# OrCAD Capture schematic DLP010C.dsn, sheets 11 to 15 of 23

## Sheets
11 PAGE 10 - DLPC410 - 2: size Custom
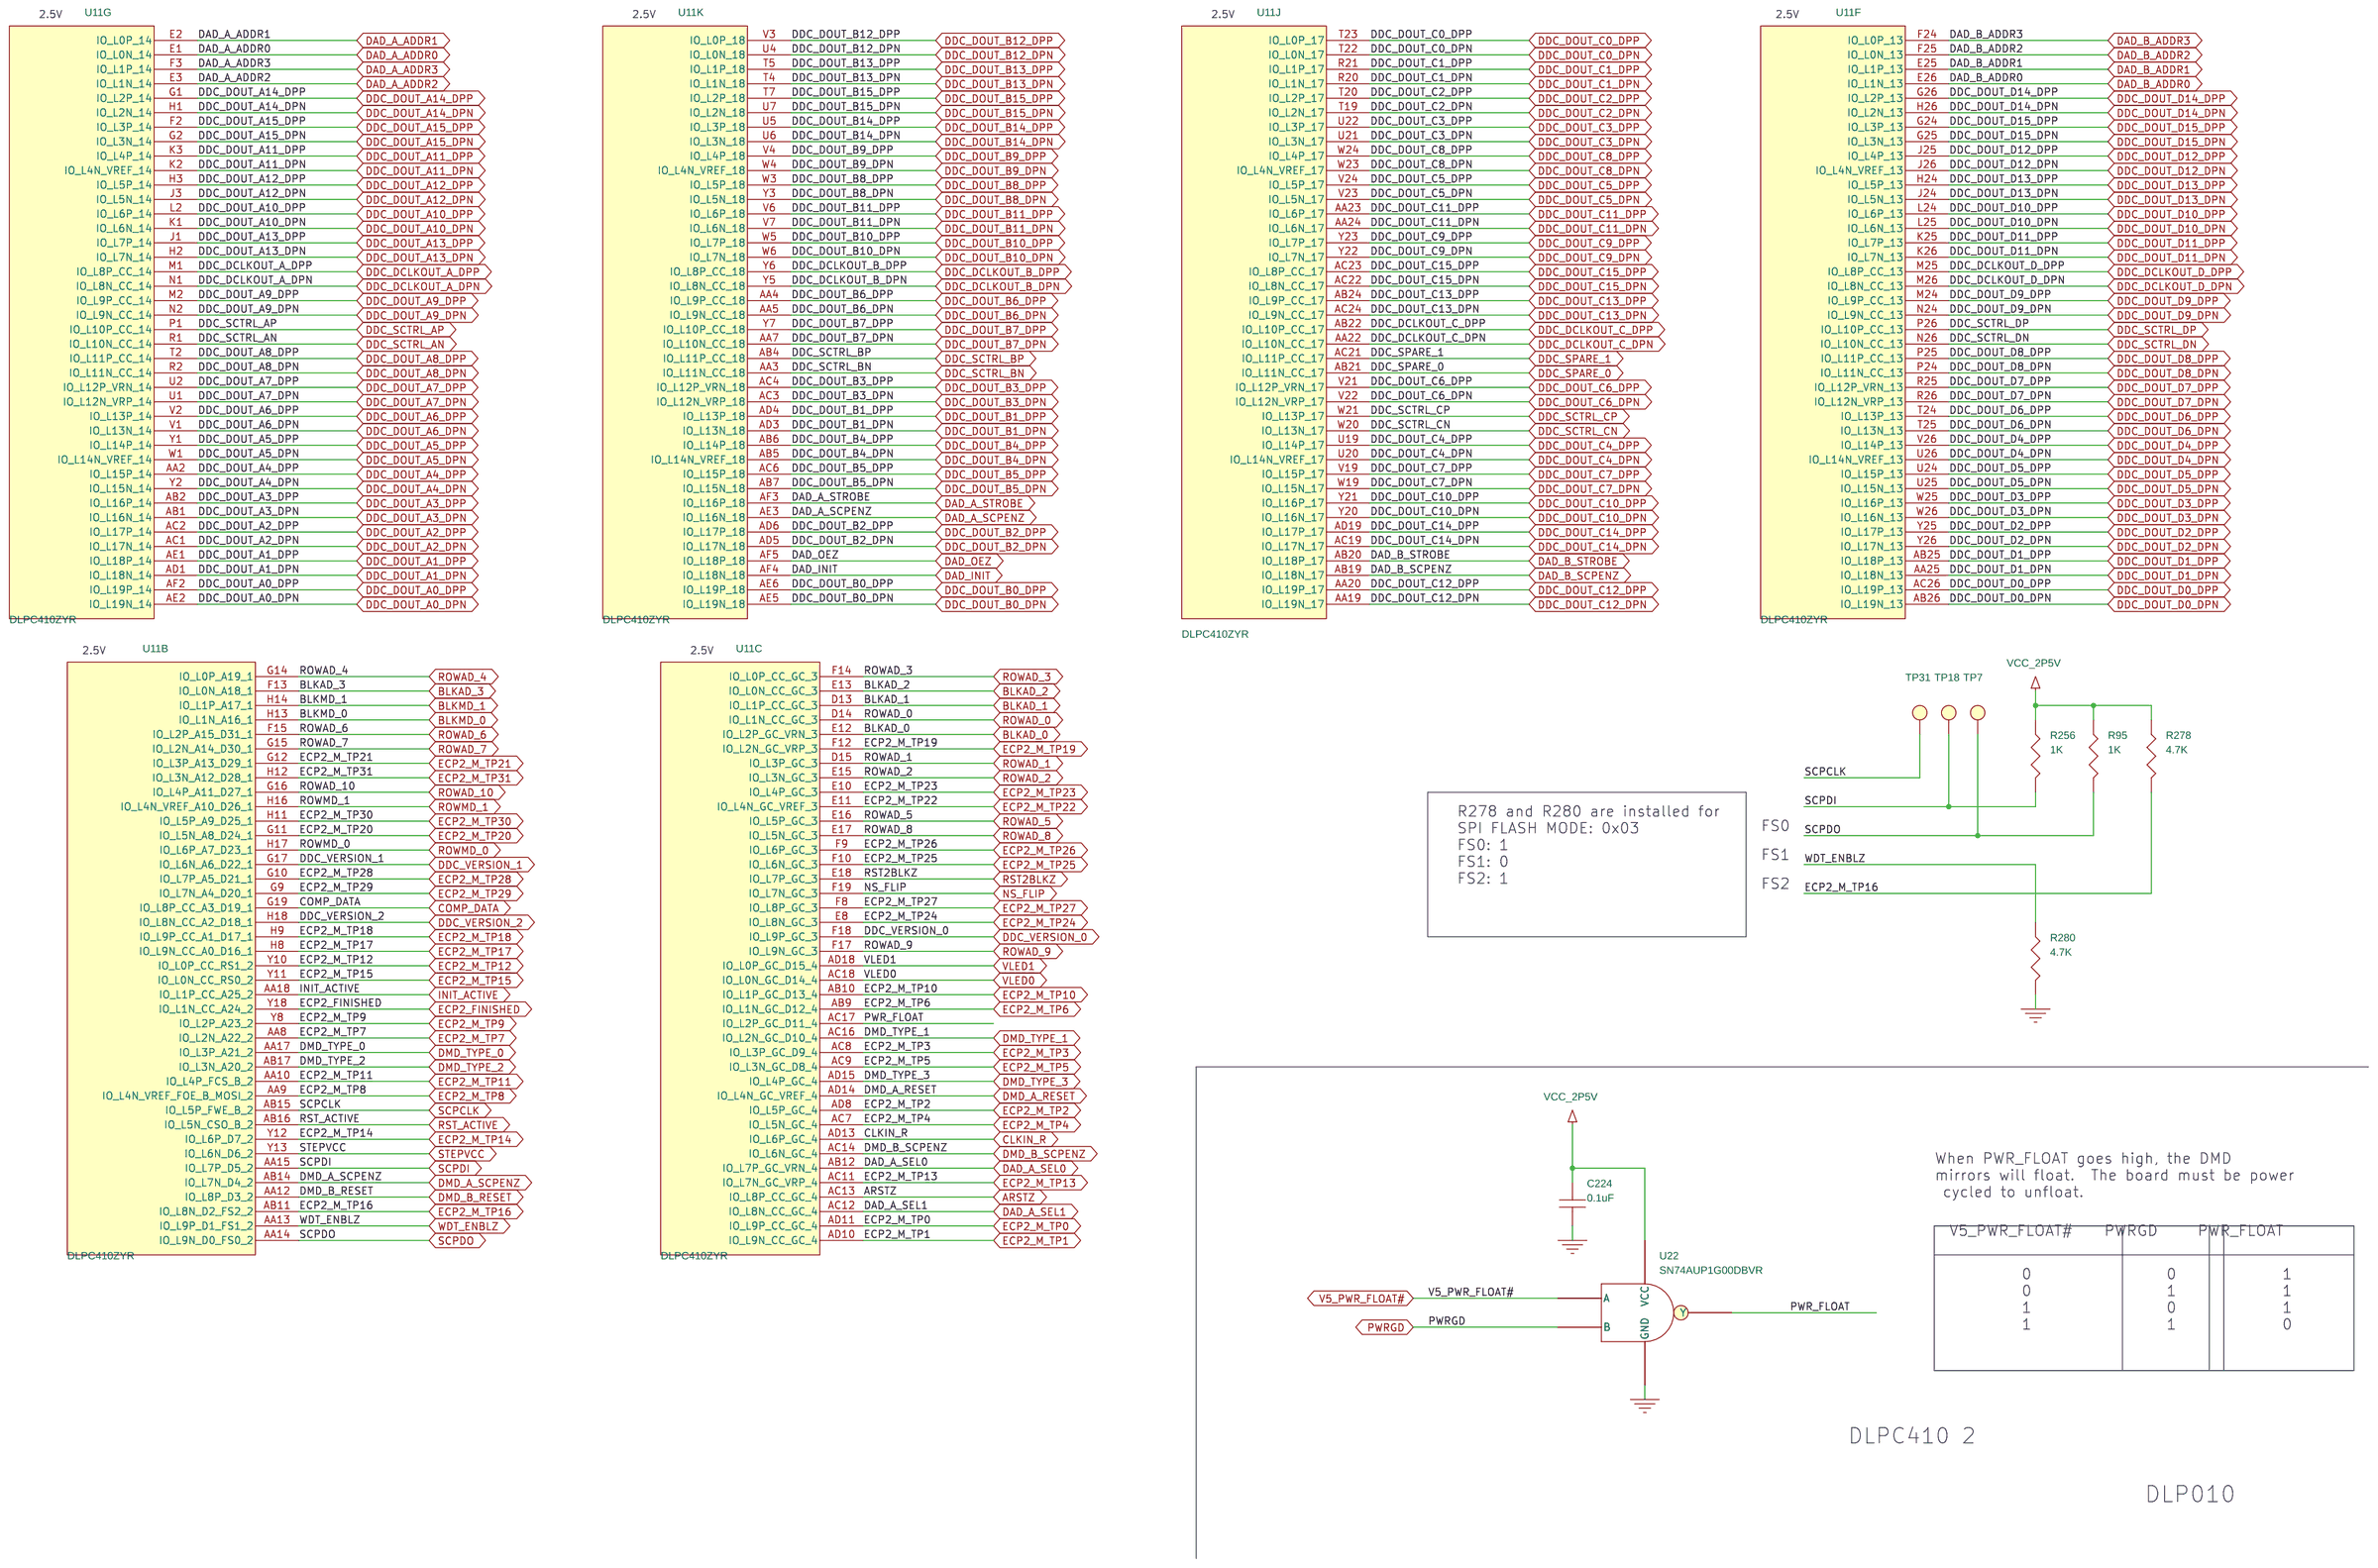
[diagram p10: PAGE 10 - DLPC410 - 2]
12 PAGE 11 - DLPC410 - 3: size Custom
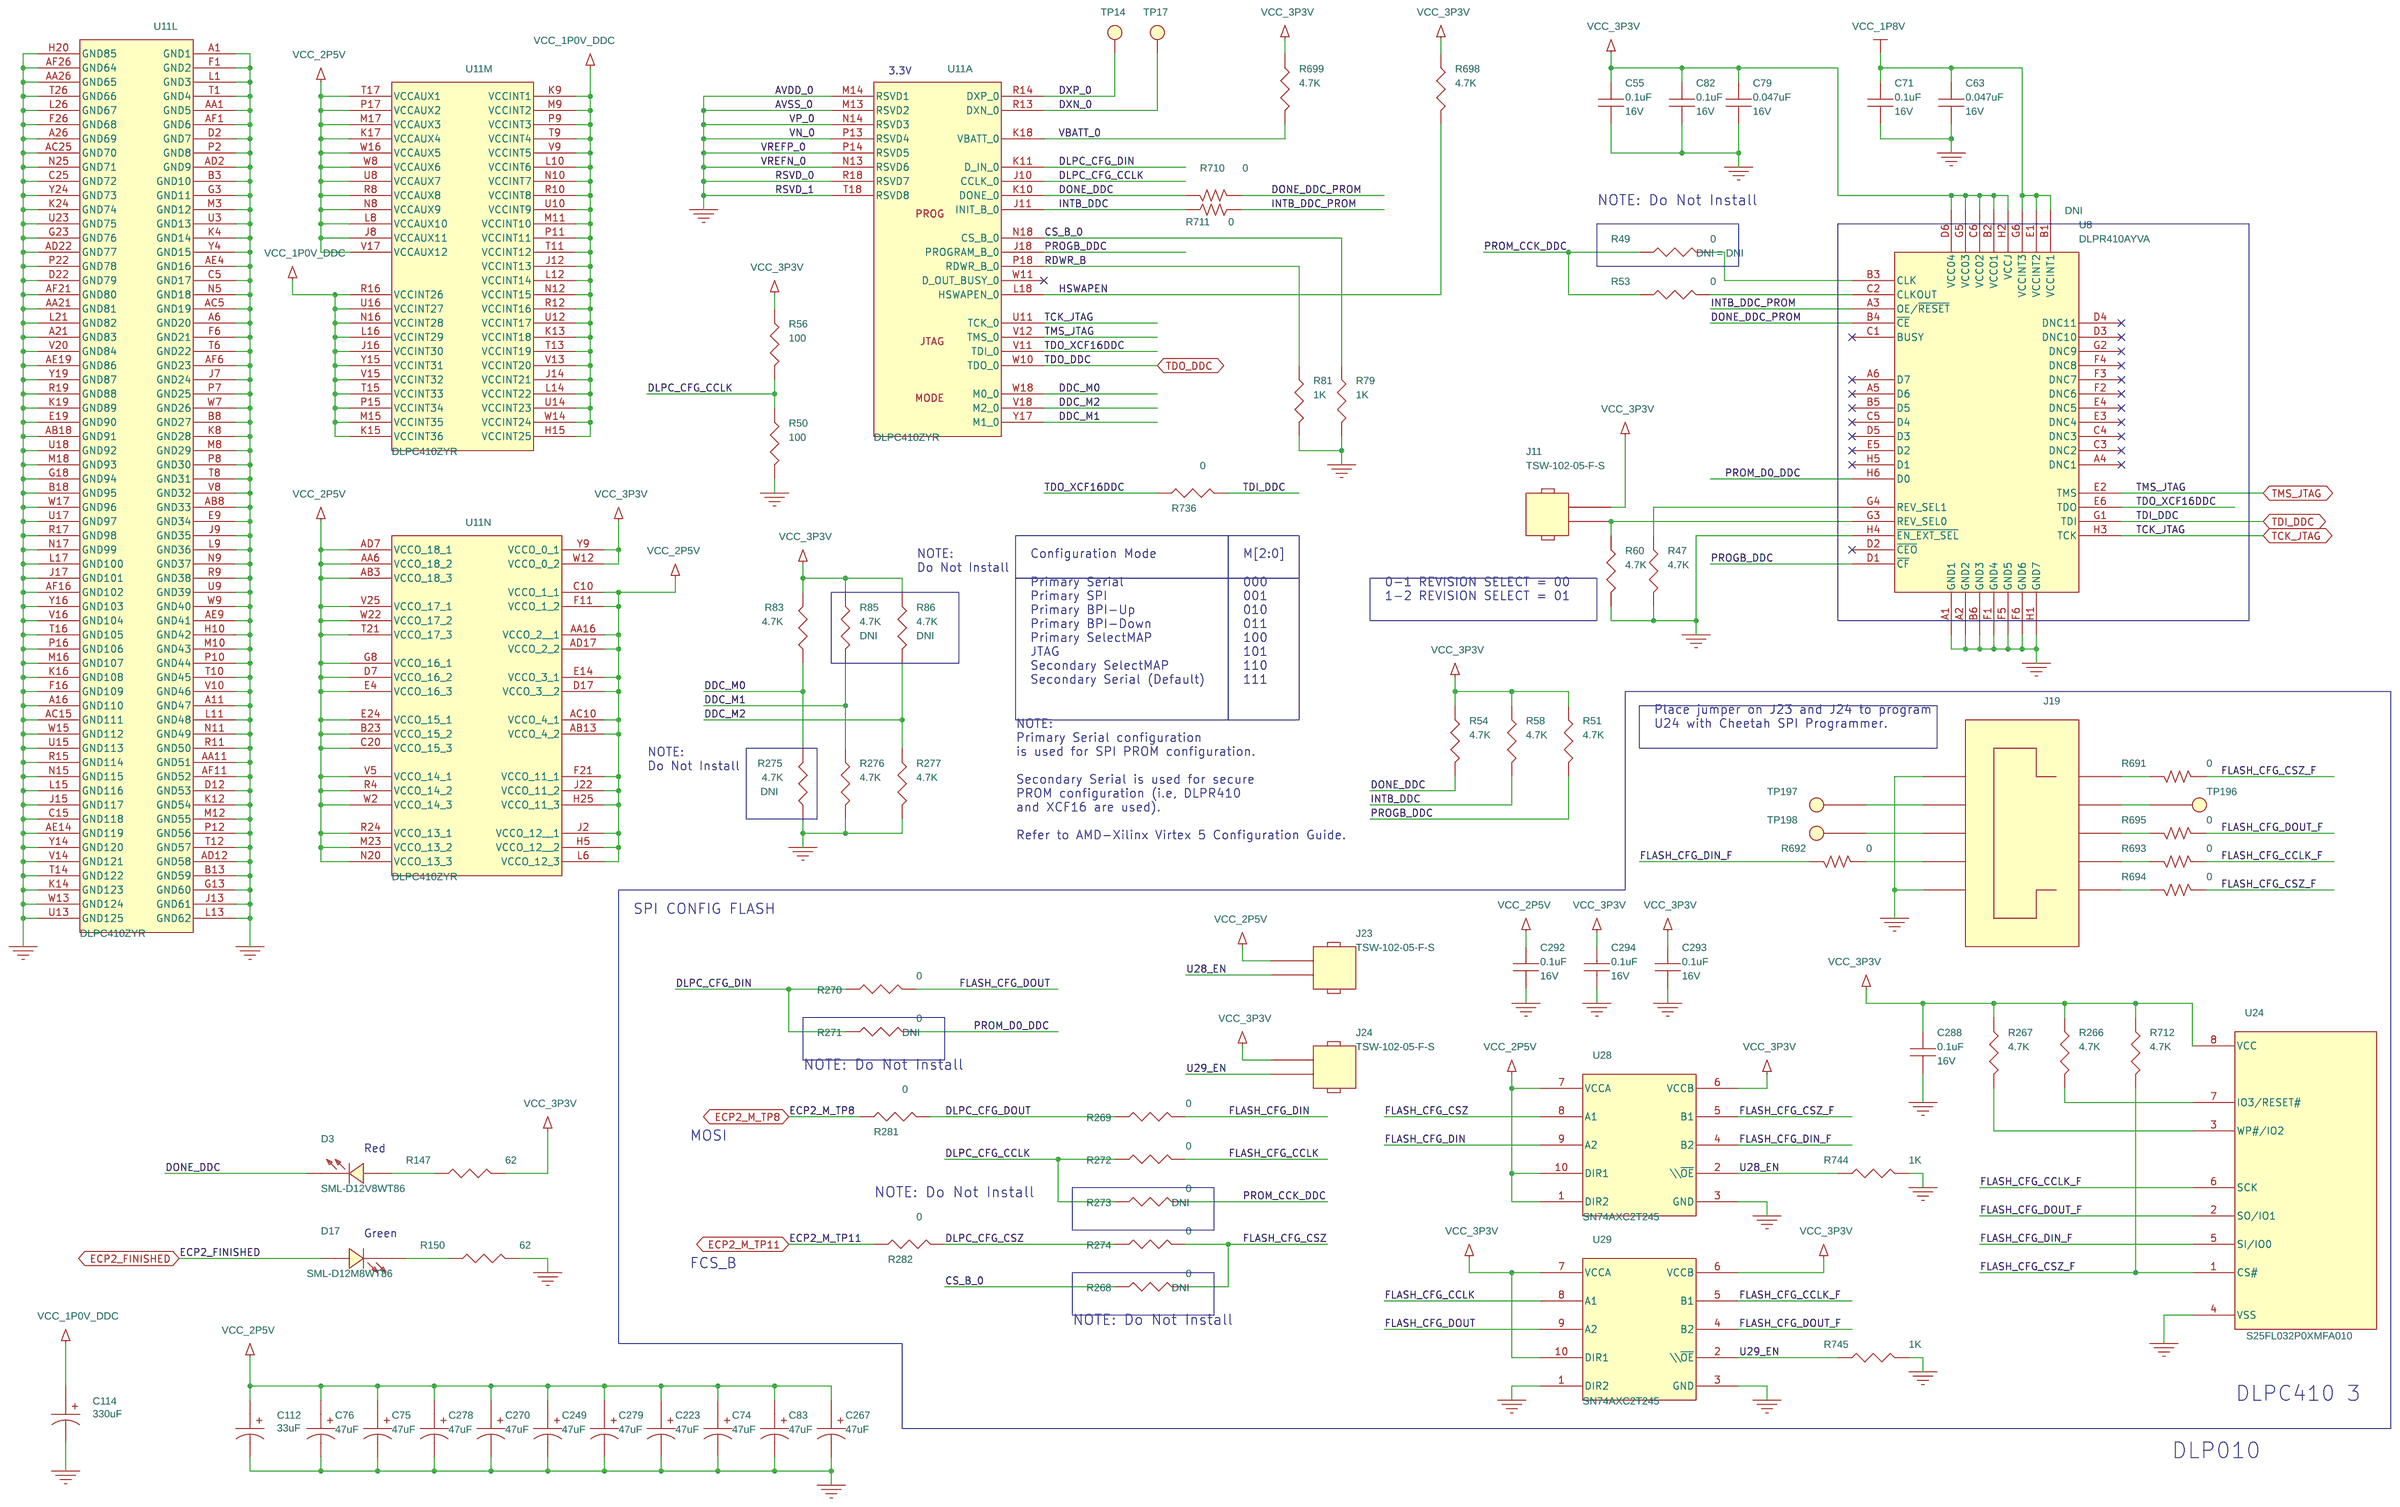
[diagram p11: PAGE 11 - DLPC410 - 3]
13 PAGE 12 - DLPA200 - A: size Custom
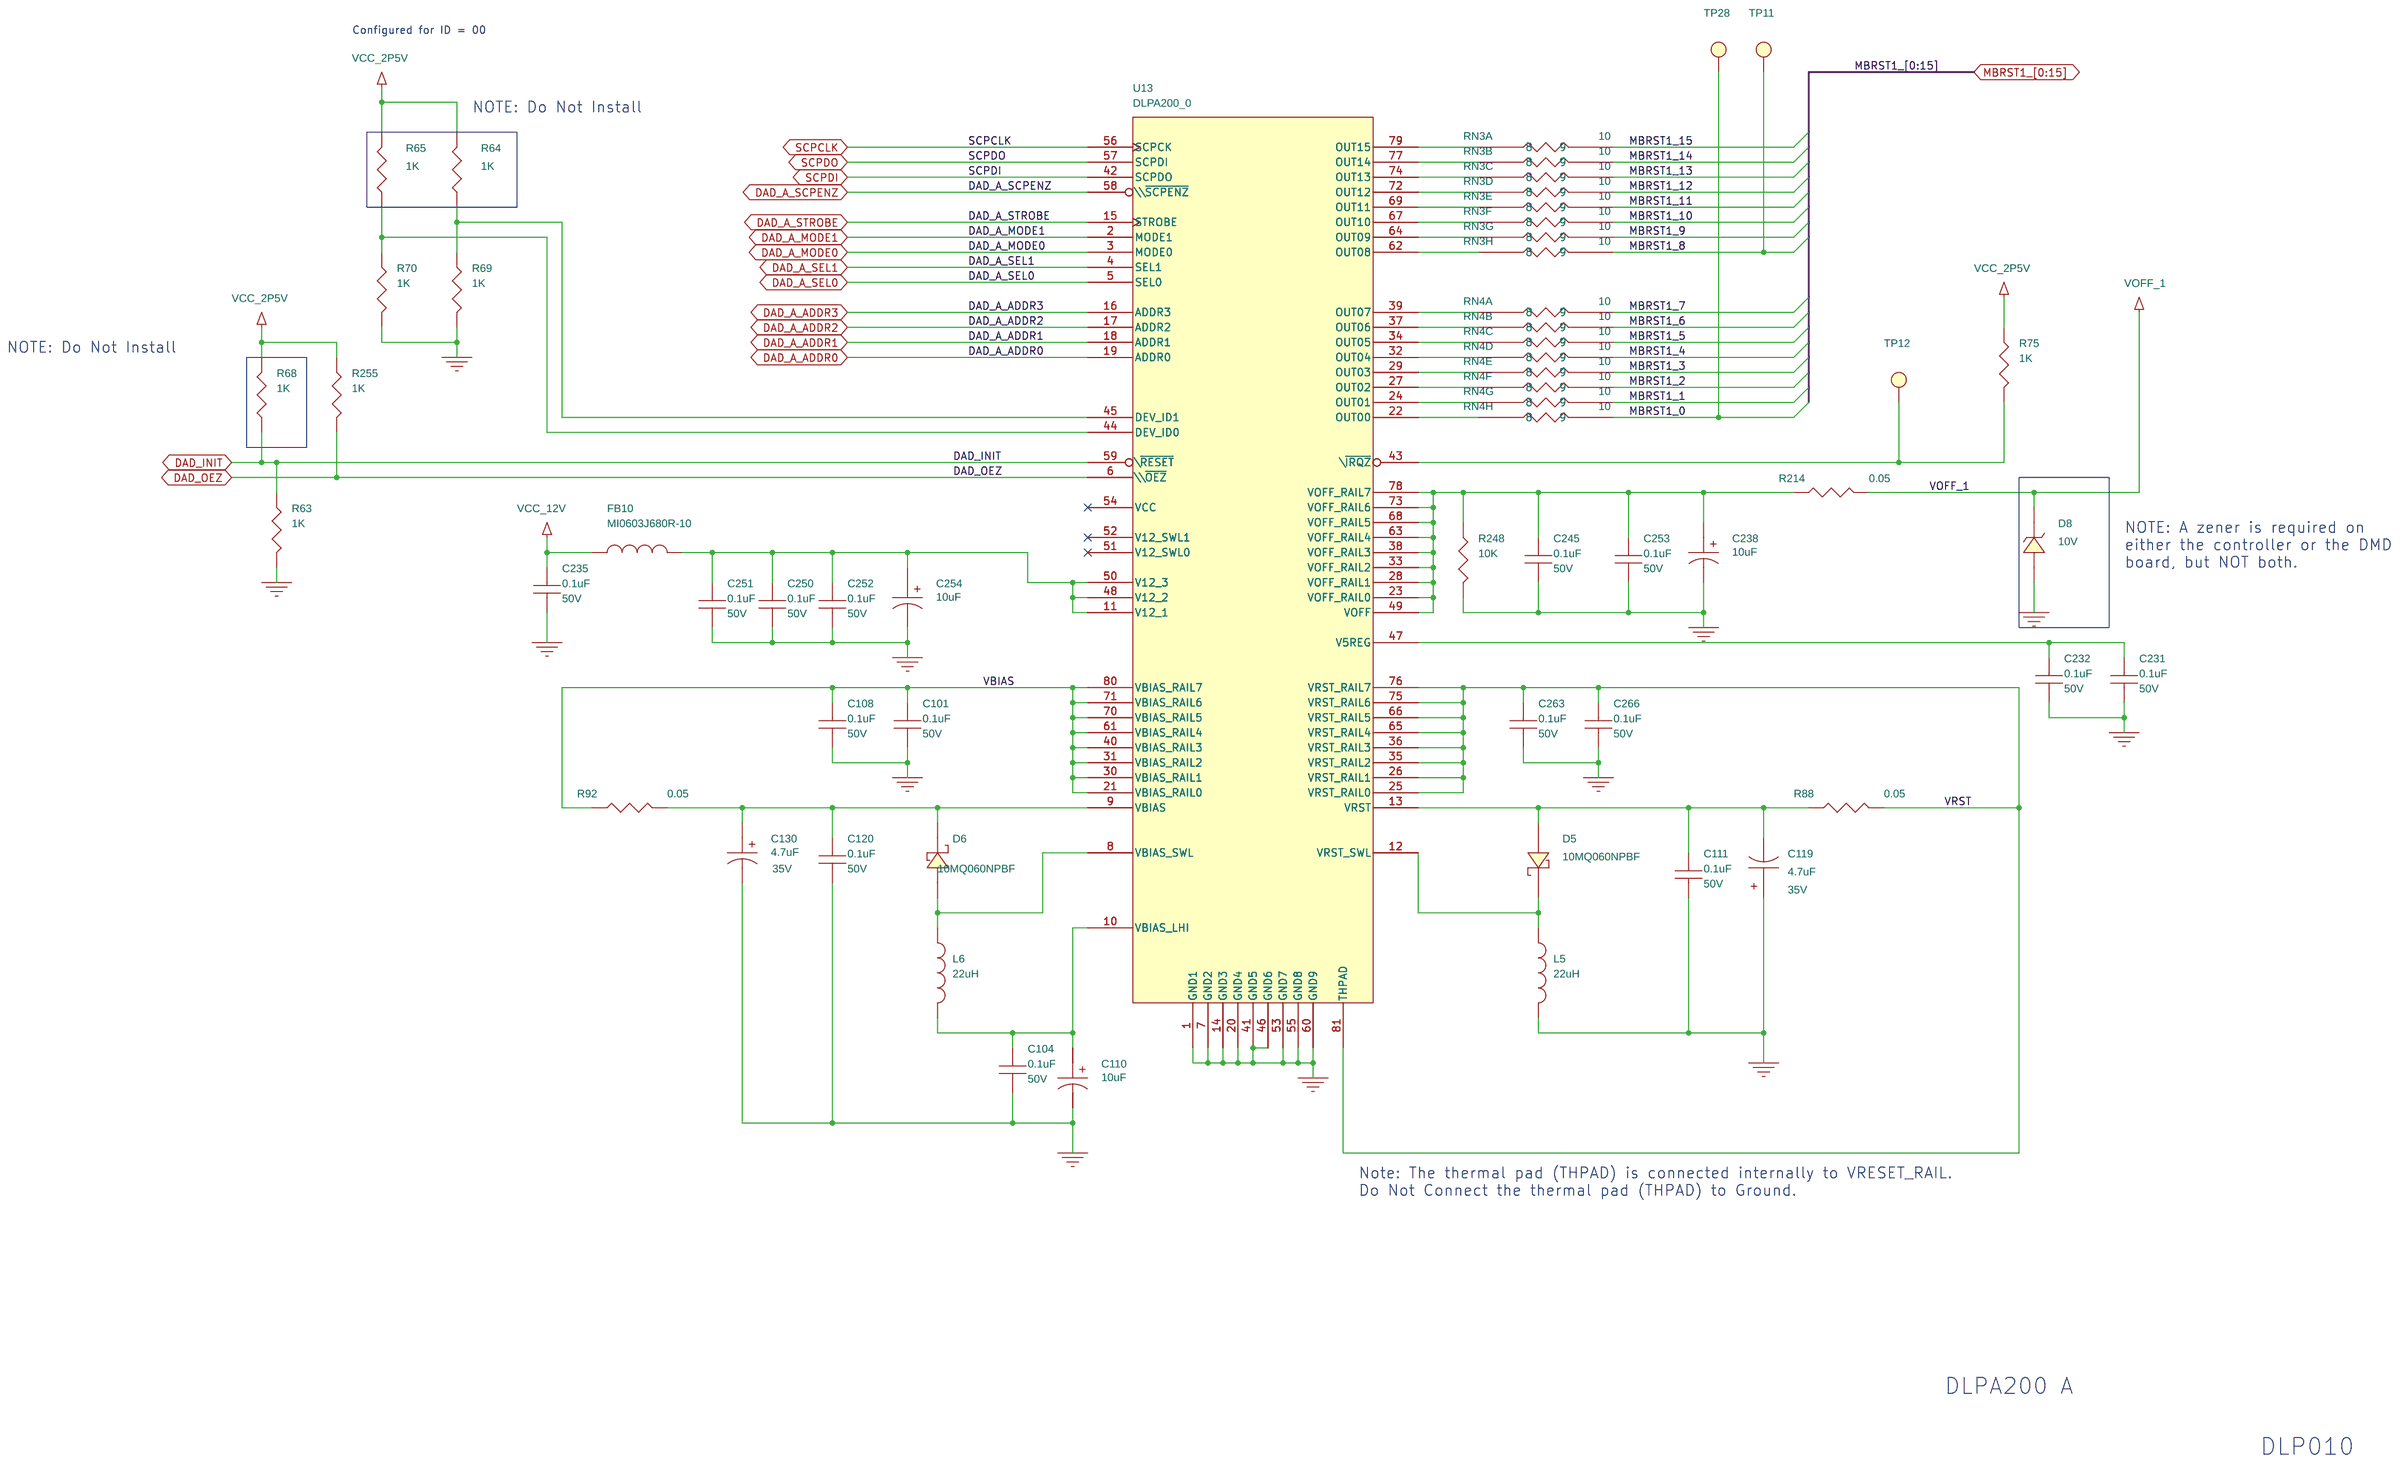
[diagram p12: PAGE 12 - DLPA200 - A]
14 PAGE 13 - DLPA200 - B: size Custom
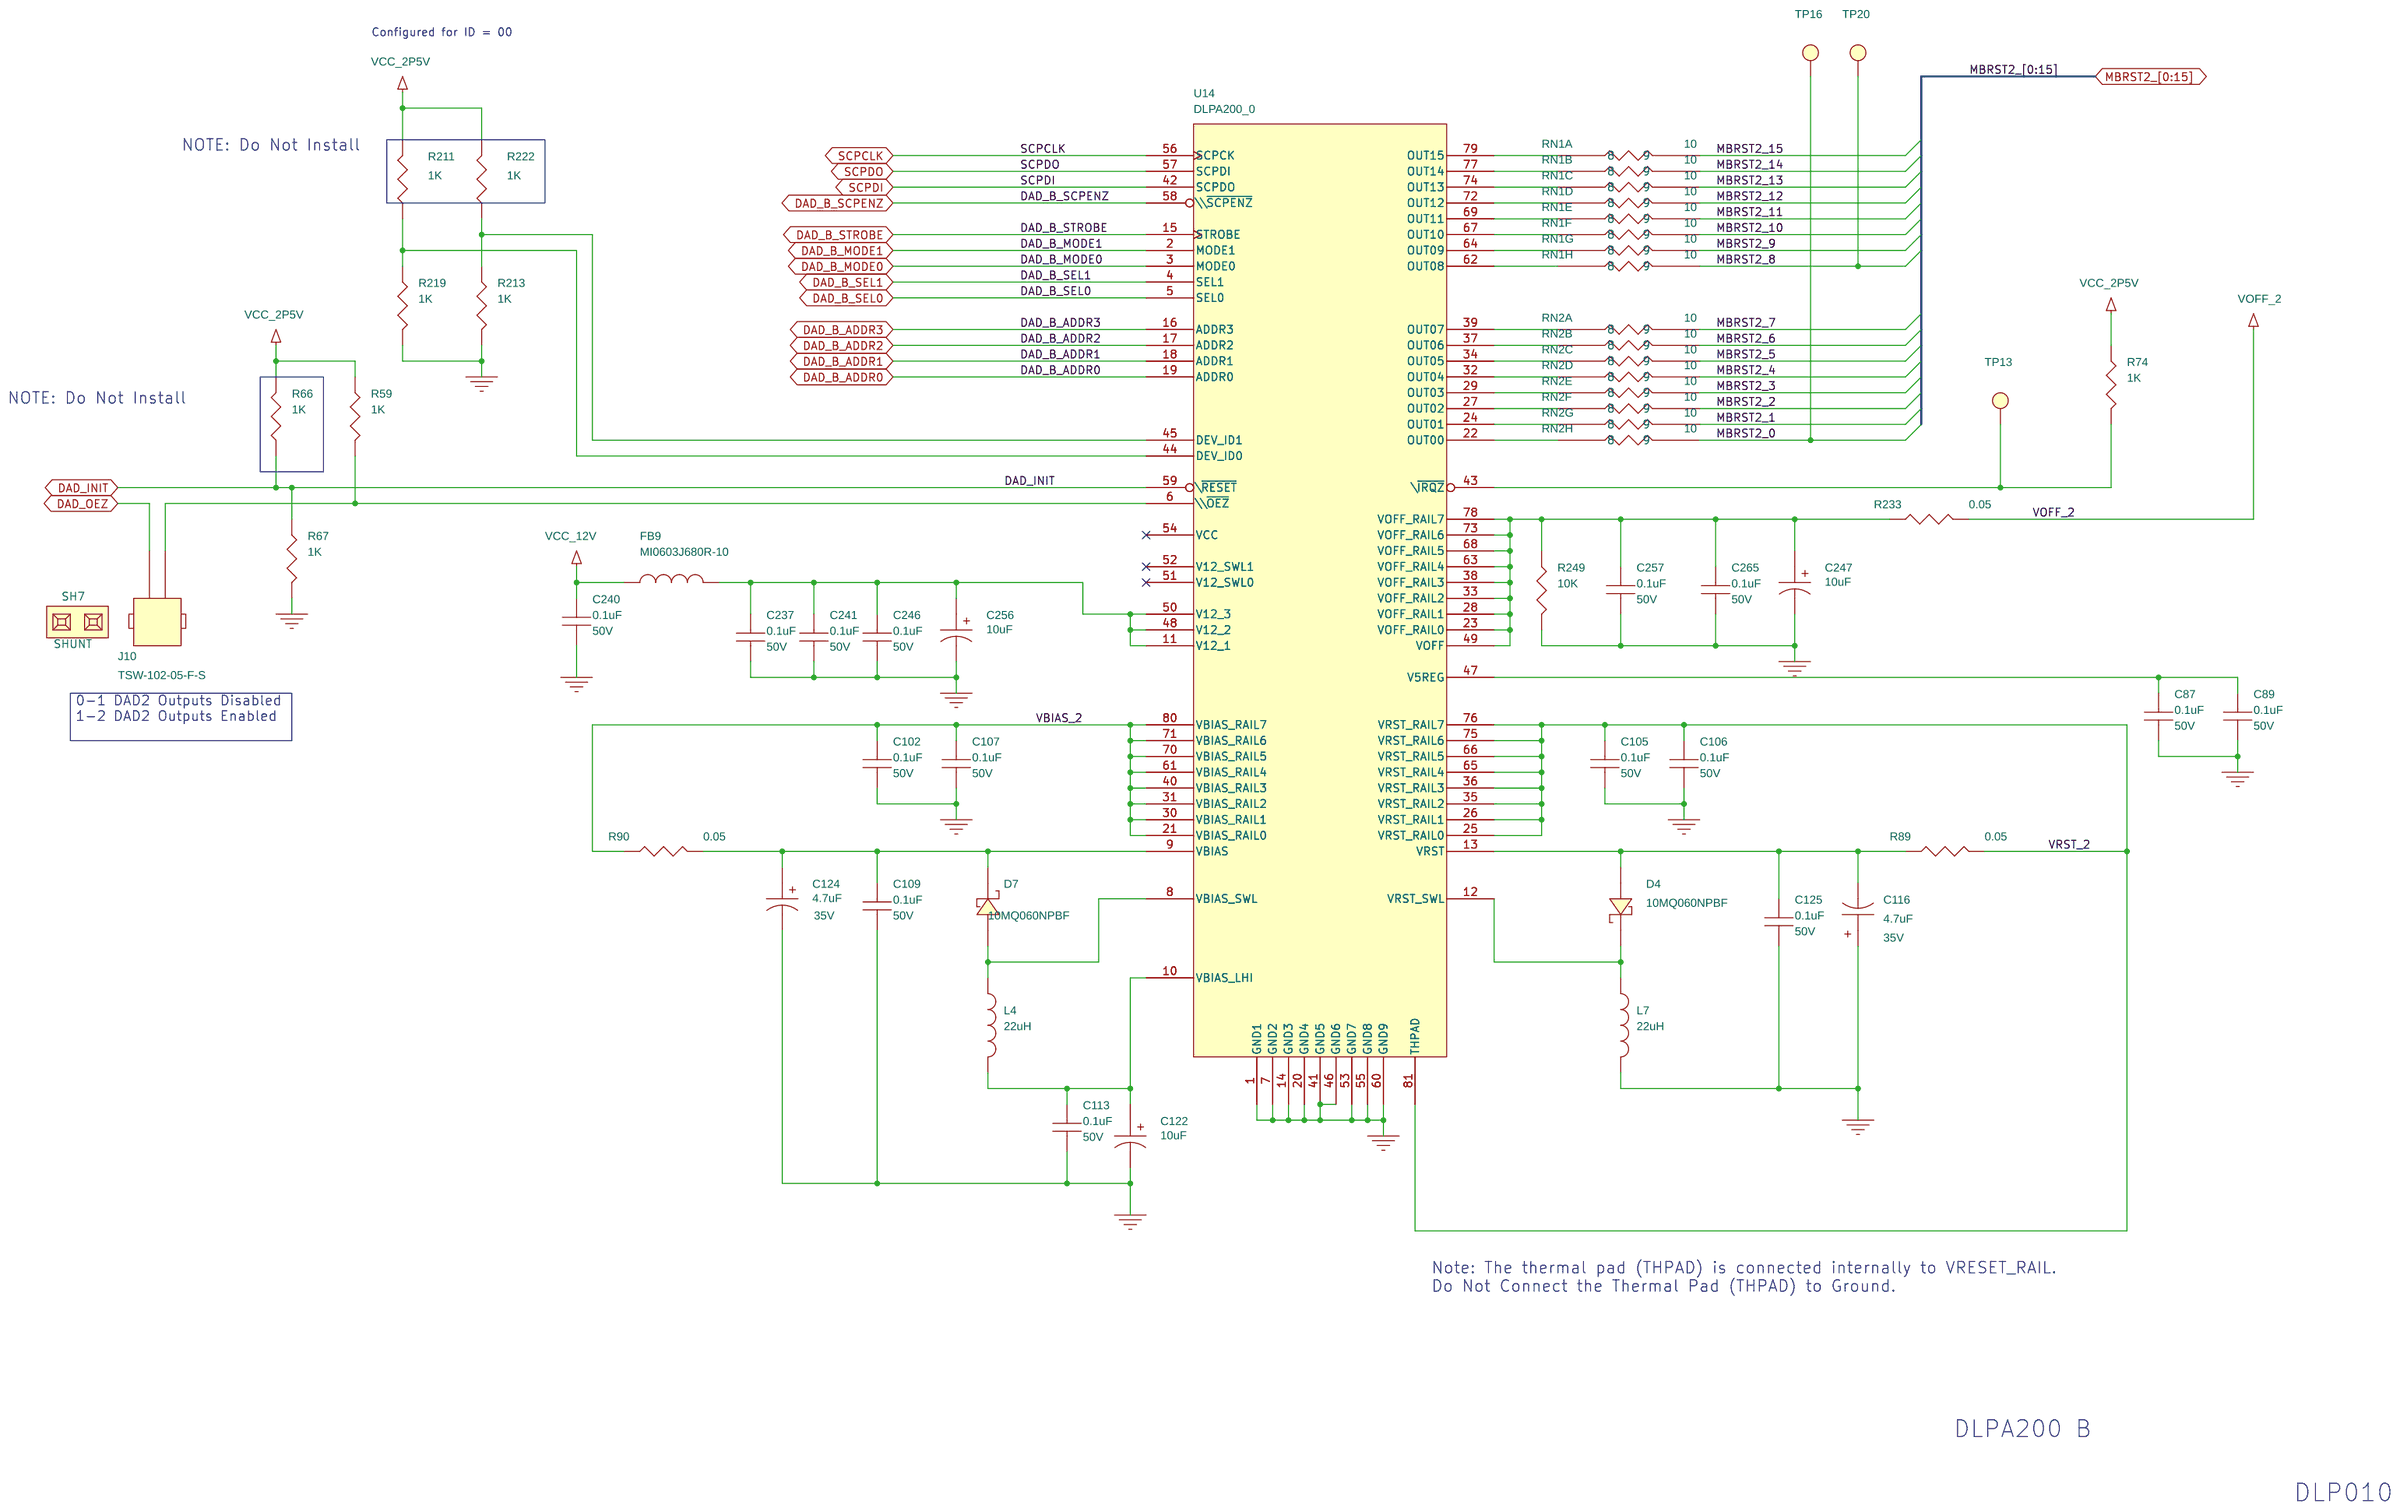
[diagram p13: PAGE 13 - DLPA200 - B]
15 PAGE 14- DMD FLEX A: size Custom
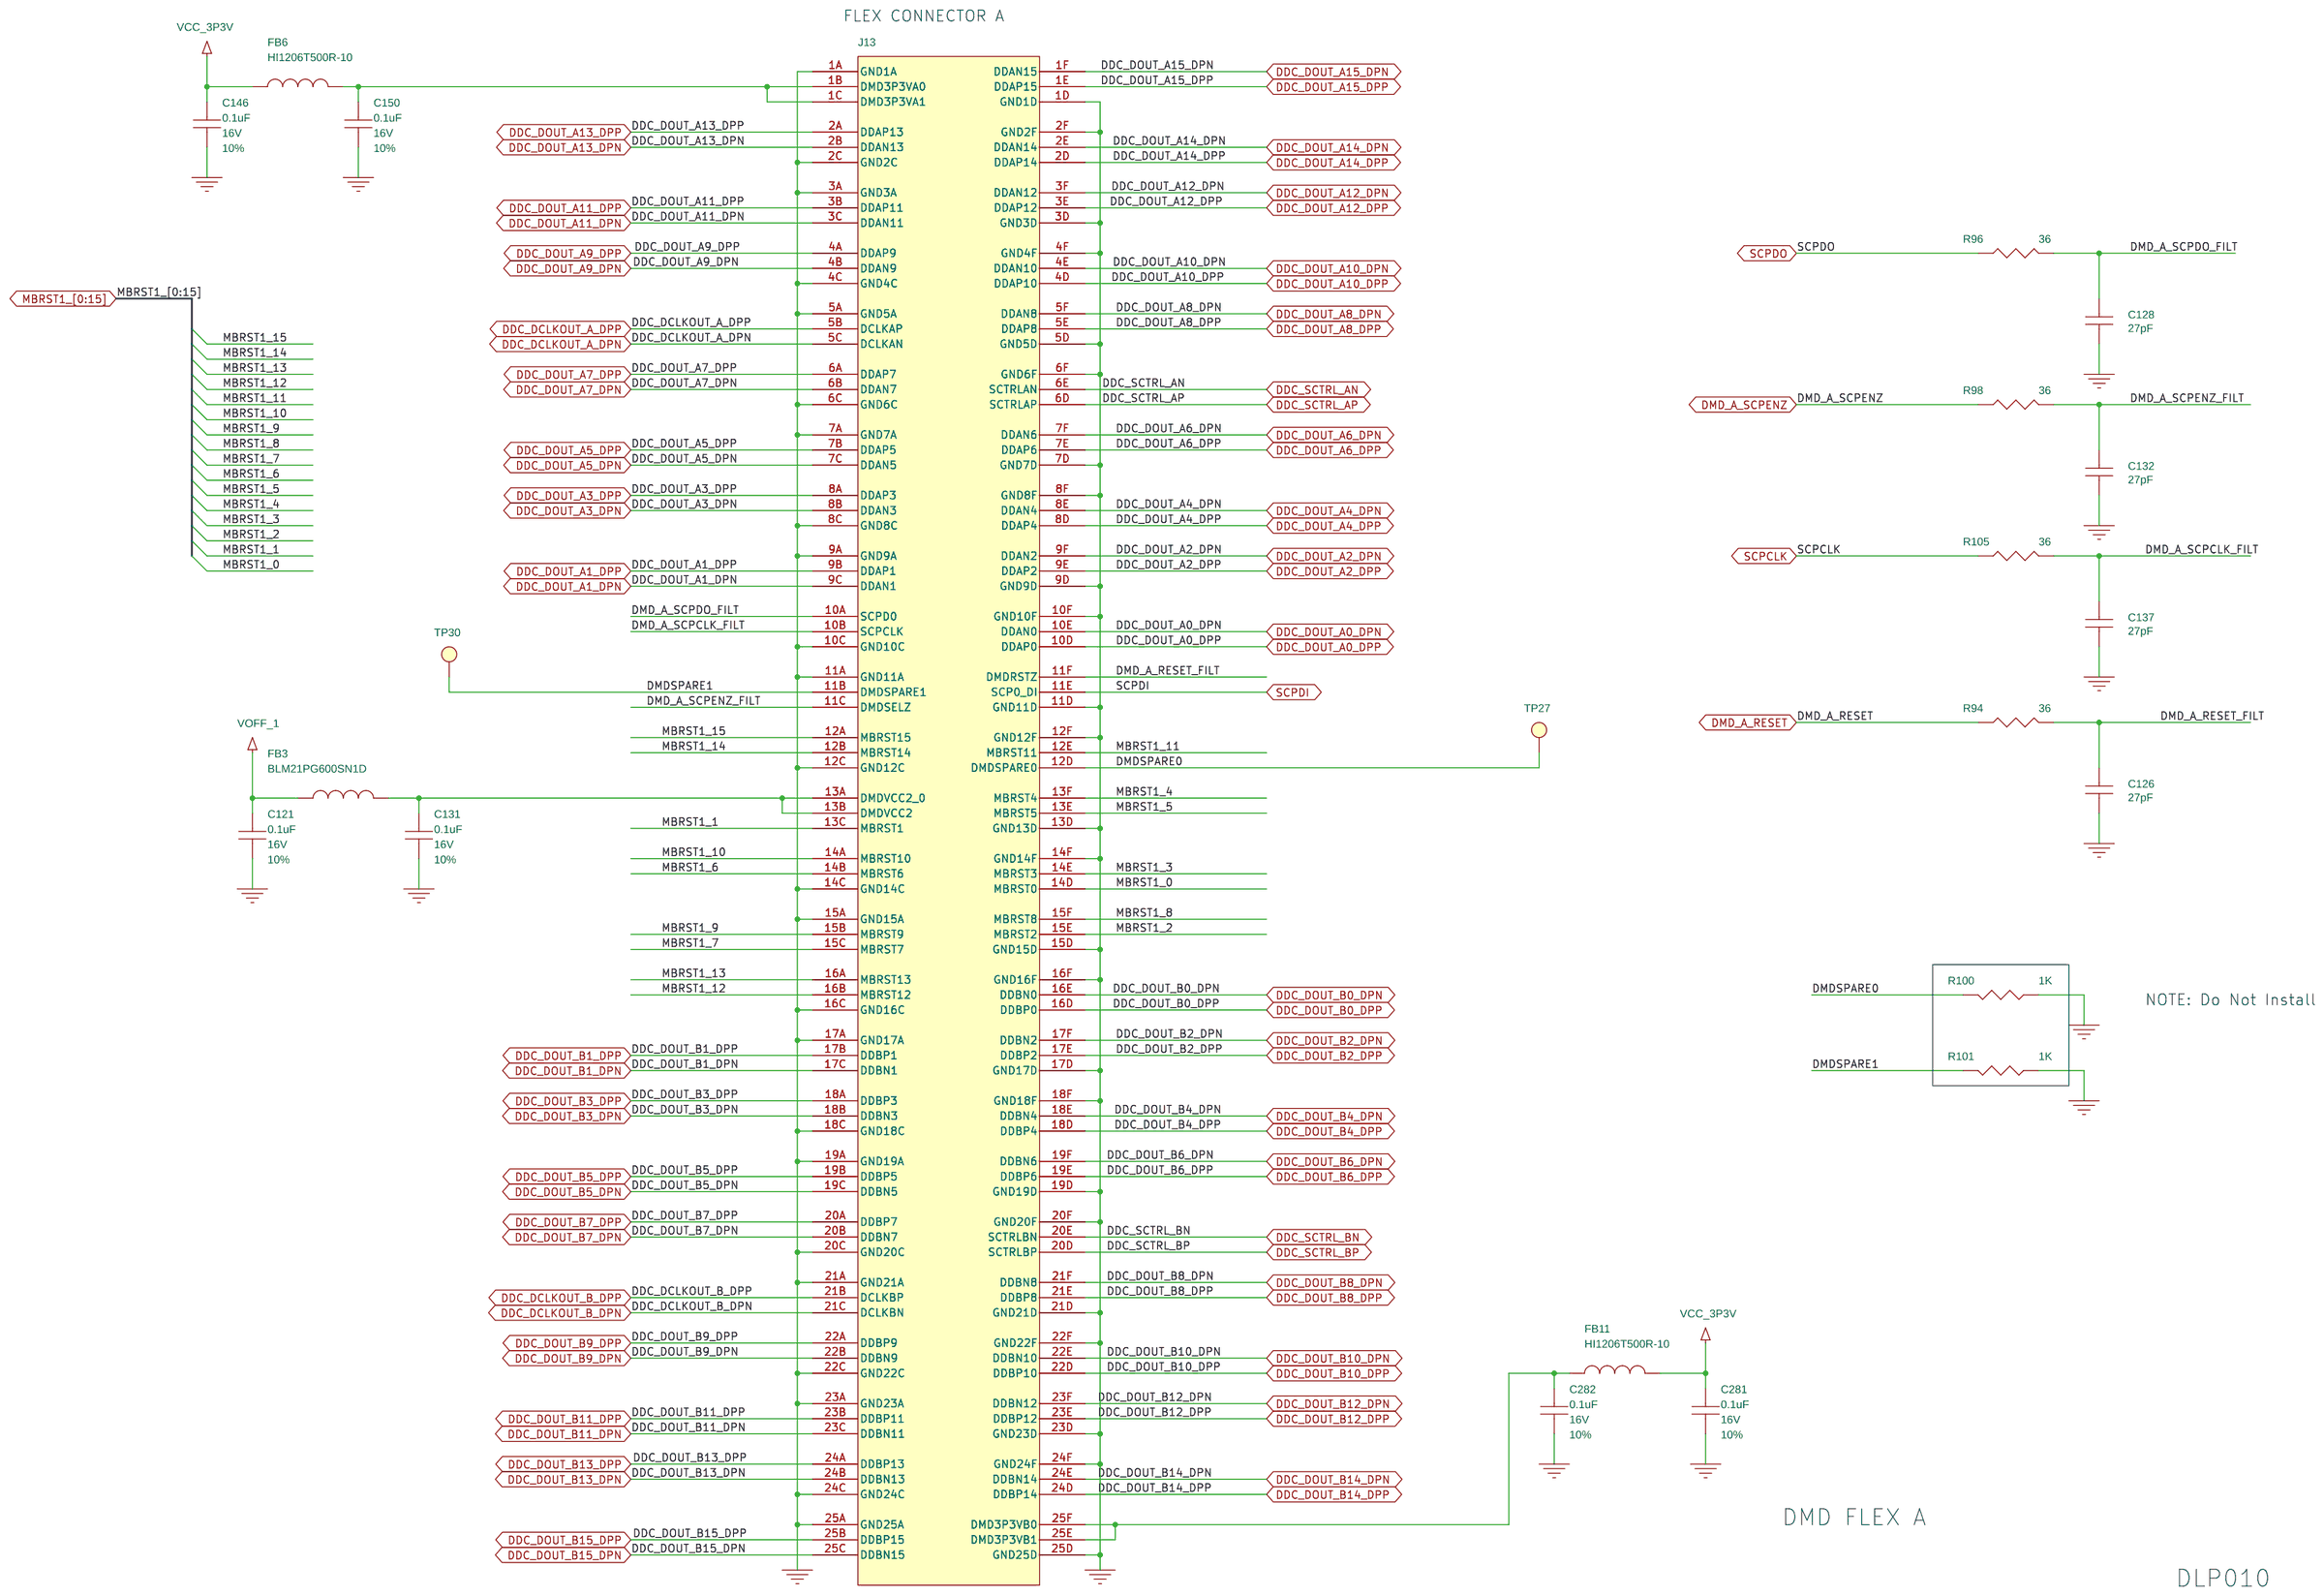
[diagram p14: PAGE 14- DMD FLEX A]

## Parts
sheet PAGE 10 - DLPC410 - 2
C224  0.1uF  [0402]
R95  1K  [0603]
R256  1K  [0603]
R278  4.7K  [0603]
R280  4.7K  [0603]
TP7  T POINT R  [25MILSQPOST]
TP18  T POINT R  [25MILSQPOST]
TP31  T POINT R  [25MILSQPOST]
U11  DLPC410ZYR  [sm_ff676]  (sections A,B,C,D,E,F,G,H,I,J,K,L,M,N,O)
U22  SN74AUP1G00DBVR  [sot23-5]
sheet PAGE 11 - DLPC410 - 3
C55  0.1uF  [0603]
C63  0.047uF  [0402]
C71  0.1uF  [0603]
C74  47uF  [tant_b]
C75  47uF  [tant_b]
C76  47uF  [tant_b]
C79  0.047uF  [0402]
C82  0.1uF  [0603]
C83  47uF  [tant_b]
C112  33uF  [tant_b]
C114  330uF  [tant_d]
C223  47uF  [tant_b]
C249  47uF  [tant_b]
C267  47uF  [tant_b]
C270  47uF  [tant_b]
C278  47uF  [tant_b]
C279  47uF  [tant_b]
C288  0.1uF  [0603]
C292  0.1uF  [0603]
C293  0.1uF  [0603]
C294  0.1uF  [0603]
D3  SML-D12V8WT86  [sm_led_0603]
D17  SML-D12M8WT86  [sm_led_0603]
J11  TSW-102-05-F-S  [jumper2]
J19  SPIconn  [SAMTEC_TST-105-01-G-D]
J23  TSW-102-05-F-S  [jumper2]
J24  TSW-102-05-F-S  [jumper2]
R47  4.7K  [0603]
R49  0  [0603]
R50  100  [0402]
R51  4.7K  [0603]
R53  0  [0603]
R54  4.7K  [0603]
R56  100  [0402]
R58  4.7K  [0603]
R60  4.7K  [0603]
R79  1K  [0603]
R81  1K  [0603]
R83  4.7K  [0603]
R85  4.7K  [0603]
R86  4.7K  [0603]
R147  62  [0603]
R150  62  [0603]
R266  4.7K  [0603]
R267  4.7K  [0603]
R268  0  [0603]
R269  0  [0603]
R270  0  [0603]
R271  0  [0603]
R272  0  [0603]
R273  0  [0603]
R274  0  [0603]
R275  4.7K  [0603]
R276  4.7K  [0603]
R277  4.7K  [0603]
R281  0  [0603]
R282  0  [0603]
R691  0  [0603]
R692  0  [0603]
R693  0  [0603]
R694  0  [0603]
R695  0  [0603]
R698  4.7K  [0603]
R699  4.7K  [0603]
R710  0  [0603]
R711  0  [0603]
R712  4.7K  [0603]
R736  0  [0603]
R744  1K  [0603]
R745  1K  [0603]
TP14  T POINT R  [25MILSQPOST]
TP17  T POINT R  [25MILSQPOST]
TP196  Testpoint_via  [TP121H71]
TP197  Testpoint_via  [TP121H71]
TP198  Testpoint_via  [TP121H71]
U8  DLPR410AYVA  [48TFBGA]
U24  S25FL032P0XMFA010  [SOIC127P790x216-8N]
U28  SN74AXC2T245  [QFN40P180X140X55-10N]
U29  SN74AXC2T245  [QFN40P180X140X55-10N]
sheet PAGE 12 - DLPA200 - A
C101  0.1uF  [0603]
C104  0.1uF  [0603]
C108  0.1uF  [0603]
C110  10uF  [tant_b]
C111  0.1uF  [0603]
C119  4.7uF  [tant_c]
C120  0.1uF  [0603]
C130  4.7uF  [tant_c]
C231  0.1uF  [0603]
C232  0.1uF  [0603]
C235  0.1uF  [0603]
C238  10uF  [tant_b]
C245  0.1uF  [0603]
C250  0.1uF  [0603]
C251  0.1uF  [0603]
C252  0.1uF  [0603]
C253  0.1uF  [0603]
C254  10uF  [tant_b]
C263  0.1uF  [0603]
C266  0.1uF  [0603]
D5  10MQ060NPBF  [sm_dio_sma]
D6  10MQ060NPBF  [sm_dio_sma]
D8  10V  [powerdi123]
FB10  MI0603J680R-10  [0603]
L5  22uH  [sm_ind_dt1608c]
L6  22uH  [sm_ind_dt1608c]
R63  1K  [0603]
R64  1K  [0603]
R65  1K  [0603]
R68  1K  [0603]
R69  1K  [0603]
R70  1K  [0603]
R75  1K  [0603]
R88  0.05  [0603]
R92  0.05  [0603]
R214  0.05  [0603]
R248  10K  [0603]
R255  1K  [0603]
RN3  10  [sm_rp8x0603]  (sections A,B,C,D,E,F,G,H)
RN4  10  [sm_rp8x0603]  (sections A,B,C,D,E,F,G,H)
TP11  T POINT R  [25MILSQPOST]
TP12  T POINT R  [25MILSQPOST]
TP28  T POINT R  [25MILSQPOST]
U13  DLPA200_0  [TQFP80]
sheet PAGE 13 - DLPA200 - B
C87  0.1uF  [0603]
C89  0.1uF  [0603]
C102  0.1uF  [0603]
C105  0.1uF  [0603]
C106  0.1uF  [0603]
C107  0.1uF  [0603]
C109  0.1uF  [0603]
C113  0.1uF  [0603]
C116  4.7uF  [tant_c]
C122  10uF  [tant_b]
C124  4.7uF  [tant_c]
C125  0.1uF  [0603]
C237  0.1uF  [0603]
C240  0.1uF  [0603]
C241  0.1uF  [0603]
C246  0.1uF  [0603]
C247  10uF  [tant_b]
C256  10uF  [tant_b]
C257  0.1uF  [0603]
C265  0.1uF  [0603]
D4  10MQ060NPBF  [sm_dio_sma]
D7  10MQ060NPBF  [sm_dio_sma]
FB9  MI0603J680R-10  [0603]
J10  TSW-102-05-F-S  [jumper2]
L4  22uH  [sm_ind_dt1608c]
L7  22uH  [sm_ind_dt1608c]
R59  1K  [0603]
R66  1K  [0603]
R67  1K  [0603]
R74  1K  [0603]
R89  0.05  [0603]
R90  0.05  [0603]
R211  1K  [0603]
R213  1K  [0603]
R219  1K  [0603]
R222  1K  [0603]
R233  0.05  [0603]
R249  10K  [0603]
RN1  10  [sm_rp8x0603]  (sections A,B,C,D,E,F,G,H)
RN2  10  [sm_rp8x0603]  (sections A,B,C,D,E,F,G,H)
SH7  SHUNT
TP13  T POINT R  [25MILSQPOST]
TP16  T POINT R  [25MILSQPOST]
TP20  T POINT R  [25MILSQPOST]
U14  DLPA200_0  [TQFP80]
sheet PAGE 14- DMD FLEX A
C121  0.1uF  [0603]
C126  27pF  [0603]
C128  27pF  [0603]
C131  0.1uF  [0603]
C132  27pF  [0603]
C137  27pF  [0603]
C146  0.1uF  [0603]
C150  0.1uF  [0603]
C281  0.1uF  [0603]
C282  0.1uF  [0603]
FB3  BLM21PG600SN1D  [0805]
FB6  HI1206T500R-10  [1206]
FB11  HI1206T500R-10  [1206]
J13  7840-LVDS-DMD  [sm_conn_8397_board]
R94  36  [0603]
R96  36  [0603]
R98  36  [0603]
R100  1K  [0603]
R101  1K  [0603]
R105  36  [0603]
TP27  T POINT R  [25MILSQPOST]
TP30  T POINT R  [25MILSQPOST]

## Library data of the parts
C224 = CAP_NP: Manuf: Kemet; PartNumber: C0402C104K9PACTU; ROOM: ECP2; TempCoeff: X5R; Voltage: 6.3V
R95 R256 = R_v2: Manuf: Panasonic; PartNumber: ERJ-3GEYJ102V; ROOM: ECP2; Tolerance: %1
R47 R51 R54 R58 R60 R83 R266 R267 R276-R278 R280 R698 R699 R712 = R_v2: Manuf: Panasonic; PartNumber: ERJ-3GEYJ472V; ROOM: DDC4100; Tolerance: %1
TP7 TP18 TP31 = T_POINT_R: DNI: DNI; Manuf: Not-a-part; PartNumber: Not-a-part; ROOM: ECP2
U11 = XC5VLX30FF676: Manuf: Texas Instruments; ROOM: DDC4100
U22 = SN74AUP1G00DBVR: Manuf: Texas Instruments
C55 C71 C82 C288 C292-C294 = CAP_NP: Manuf: Kemet; PartNumber: C0603C104K4RACTU; ROOM: DDC4100; Tolerance: 10%; Voltage: 16V
C63 C79 = CAP_NP: Manuf: TDK; PartNumber: C1005X7R1C473K; ROOM: DDC4100; Tolerance: 10%; Voltage: 16V
C74-C76 C83 C223 C249 C267 C270 C278 C279 = CAP_POL: Manuf: Kemet; PartNumber: T520B476M006ATE070; ROOM: DDC4110_BYPASS
C112 = CAP_POL: Manuf: Kemet; PartNumber: T520B336M006ATE040; ROOM: DDC4110_BYPASS; Tolerance: 20%; Voltage: 6.3V
C114 = CAP_POL: Manuf: Kemet; PartNumber: T520V337M2R5ATE025; ROOM: DDC4110_BYPASS; Tolerance: 20%; Voltage: 2.5V
D3 D17 = LED: Manuf: ROHM; ROOM: USB
J11 = HEADER_2: Manuf: Samtec; PartNumber: TSW-102-07-F-S; ROOM: DDC4100
J19 = SPI_Connector: MFG: Samtec; Manuf: Samtec; PART NUMBER: TST-105-01-G-D; PartNumber: TST-105-01-G-D
J23 J24 = HEADER_2: Manuf: Samtec; PartNumber: TSW-102-07-F-S; ROOM: USB
R49 R268 R271 R273 = R_v2: DNI: DNI; Manuf: Panasonic; Notes: DNI; PartNumber: ERJ-3GEY0R00V; ROOM: DDC4100; Tolerance: %1
R50 R56 = R_v2: Manuf: Panasonic; PartNumber: ERJ-2RKF1000X; ROOM: DDC4100
R53 R269 R270 R272 R274 R281 R282 R736 = R_v2: Manuf: Panasonic; PartNumber: ERJ-3GEY0R00V; ROOM: DDC4100; Tolerance: %1
R79 R81 = R_v2: Manuf: Panasonic; PartNumber: ERJ-3GEYJ102V; ROOM: DDC4100; Tolerance: %1
R85 R86 R275 = R_v2: DNI: DNI; Manuf: Panasonic; Notes: DNI; PartNumber: ERJ-3GEYJ472V; ROOM: DDC4100; Tolerance: %1
R147 R150 = R_v2: Manuf: Panasonic; PartNumber: ERJ-3GEYJ620V; ROOM: DDC4100; Tolerance: %5
R691-R695 R710 R711 = R: DigiKey Part Number: 1276-3480-1-ND; MFG: Vishay Dale; Manuf: Vishay Dale; PART NUMBER: CRCW06030000Z0EAC; PartNumber: CRCW06030000Z0EAC; Rating: 0.1 W
R744 R745 = R_v2: Manuf: Panasonic; PartNumber: ERJ-3GEYJ102V; Tolerance: %1
TP14 TP17 = T_POINT_R: DNI: DNI; Manuf: Not-a-part; PartNumber: Not-a-part; ROOM: DDC4100
TP196-TP198 = Testpoint: DNI: DNI; MFG: Not-a-part; Manuf: Not-a-part; Notes: 28mil_via; PART NUMBER: Not-a-part; PartNumber: Not-a-part
U8 = DFM-XCF08P-FSG48C_3: DNI: DNI; Manuf: Texas Instruments; ROOM: DDC4100
U24 = S25FL128LAGMFM010: IC FLASH 32MBIT SPI/QUAD 8SOIC; Digikey Part Number: 428-4396-ND; MFG: Infineon Technologies; Manuf: Infineon Technologies; Manufacturer: Cypress
U28 U29 = SN74AXC2T245: MFG: Texas Instruments; Manuf: Texas Instruments; PartNumber: SN74AXC2T245RSWR
C101 C104 C108 C111 C120 C231 C232 C235 C245 C250-C253 C263 C266 = CAP_NP: Manuf: TDK; PartNumber: C1608X7R1H104K; ROOM: DAD A; Voltage: 50V
C110 C238 C254 = CAP_POL: Manuf: AVX; PartNumber: TPSB106K020R1000; ROOM: DAD A; Voltage: 20V
C119 C130 = CAP_POL: Manuf: AVX; PartNumber: TPSC475K035R0600; ROOM: DAD A; Voltage: 35V
D5 D6 = DIODE_SCHOTTKY: If: 1.5A; Manuf: Vishay; PartNumber: 10MQ060NTRPBF; ROOM: DAD A; Vf: 60V
D8 = DIODE_ZENER: Manuf: DIODES INC; PartNumber: DFLZ10-7; Power: DMD
FB10 = INDUCTOR: Current: 1A; Impedance: 68; Manuf: Steward; ROOM: DAD A
L5 L6 = INDUCTOR: Manuf: CoilCraft; PartNumber: DT1608c-223MLC; ROOM: DAD A
R63 R69 R70 R75 R255 = R_v2: Manuf: Panasonic; PartNumber: ERJ-3GEYJ102V; ROOM: DAD A; Tolerance: %1
R64 R65 R68 = R_v2: DNI: DNI; Manuf: Panasonic; Notes: DNI; PartNumber: ERJ-3GEYJ102V; ROOM: DAD A
R88 R92 R214 = R_v2: Manuf: Panasonic; PartNumber: ERJ-3GEY0R00V; ROOM: DAD A; Tolerance: %1
R248 = R_v2: Manuf: Panasonic; PartNumber: ERJ-3GEYJ103V; ROOM: DAD A; Tolerance: %1
RN3 RN4 = RSNETWORKx8: Manuf: CTS; PartNumber: 742C163100JP; ROOM: DAD A
TP11 TP12 TP28 = T_POINT_R: DNI: DNI; Manuf: Not-a-part; PartNumber: Not-a-part; ROOM: DAD A
U13 = DAD2000_0: Manuf: Texas Instruments; PartNumber: DLPA200PFP; ROOM: DAD A
C87 C89 C102 C105-C107 C109 C113 C125 C237 C240 C241 C246 C257 C265 = CAP_NP: Manuf: TDK; PartNumber: C1608X7R1H104K; ROOM: DAD B; Voltage: 50V
C116 C124 = CAP_POL: Manuf: AVX; PartNumber: TPSC475K035R0600; ROOM: DAD B; Voltage: 35V
C122 C247 C256 = CAP_POL: Manuf: AVX; PartNumber: TPSB106K020R1000; ROOM: DAD B; Voltage: 20V
D4 D7 = DIODE_SCHOTTKY: If: 1.5A; Manuf: Vishay; PartNumber: 10MQ060NTRPBF; ROOM: DAD B; Vf: 60V
FB9 = INDUCTOR: Current: 1A; Impedance: 68; Manuf: Steward; ROOM: DAD B
J10 = HEADER_2: Manuf: Samtec; PartNumber: TSW-102-07-F-S; ROOM: DAD B
L4 L7 = INDUCTOR: Manuf: CoilCraft; PartNumber: DT1608c-223MLC; ROOM: DAD B
R59 R67 R74 R213 R219 = R_v2: Manuf: Panasonic; PartNumber: ERJ-3GEYJ102V; ROOM: DAD B; Tolerance: %1
R66 R211 R222 = R_v2: DNI: DNI; Manuf: Panasonic; Notes: DNI; PartNumber: ERJ-3GEYJ102V; ROOM: DAD B
R89 R90 R233 = R_v2: Manuf: Panasonic; PartNumber: ERJ-3GEY0R00V; ROOM: DAD B; Tolerance: %1
R249 = R_v2: Manuf: Panasonic; PartNumber: ERJ-3GEYJ103V; ROOM: DAD B; Tolerance: %1
RN1 RN2 = RSNETWORKx8: Manuf: CTS; PartNumber: 742C163100JP; ROOM: DAD B
SH7 = CON2_1: CONN SHUNT SPRING 2POS .100 GOLD; Manuf: AMP; PartNumber: 530153-2
TP13 TP16 TP20 = T_POINT_R: DNI: DNI; Manuf: Not-a-part; PartNumber: Not-a-part; ROOM: DAD B
U14 = DAD2000_0: Manuf: Texas Instruments; PartNumber: DLPA200PFP; ROOM: DAD B
C121 C131 C146 C150 C281 C282 = CAP_NP: Manuf: Kemet; PartNumber: C0603C104K4RACTU; Tolerance: 10%; Voltage: 16V
C126 C128 C132 C137 = CAP_NP: Manuf: KEMET; PartNumber: C0603C270J5GAC7867; Tolerance: C0G; Voltage: 50
FB3 = INDUCTOR: Current: 3A; Impedance: 60; Manuf: Murata
FB6 FB11 = INDUCTOR: Current: 6A; Impedance: 50ohms @ 100Mhz; Manuf: Steward
J13 = 7840-LVDS-DMD: DNI: DNI; Manuf: Amphenol; Notes: DNI - Install during test; PartNumber: 7840-002
R94 R96 R98 R105 = R_v2: Manuf: Panasonic; PartNumber: ERJ-3GEYJ360V; Tolerance: %5
R100 R101 = R_v2: DNI: DNI; Manuf: Panasonic; Notes: DNI; PartNumber: ERJ-3GEYJ102V
TP27 TP30 = T_POINT_R: DNI: DNI; Manuf: Not-a-part; PartNumber: Not-a-part

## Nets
GND: C55.2 C63.2 C71.2 C74.2 C75.2 C76.2 C79.2 C82.2 C83.2 C87.2 C89.2 C101.2 C102.2 C104.2 C105.2 C106.2 C107.2 C108.2 C109.2 C110.2 C111.2 C112.2 C113.2 C114.2 C116.1 C119.1 C120.2 C121.2 C122.2 C124.2 C125.2 C126.2 C128.2 C130.2 C131.2 C132.2 C137.2 C146.2 C150.2 C223.2 C224.2 C231.2 C232.2 C235.2 C237.2 C238.2 C240.2 C241.2 C245.2 C246.2 C247.2 C249.2 C250.2 C251.2 C252.2 C253.2 C254.2 C256.2 C257.2 C263.2 C265.2 C266.2 C267.2 C270.2 C278.2 C279.2 C281.2 C282.2 C288.2 C292.2 C293.2 C294.2 D8.1(ANODE) J13.1A(GND1A) J13.1D(GND1D) J13.2C(GND2C) J13.2F(GND2F) J13.3A(GND3A) J13.3D(GND3D) J13.4C(GND4C) J13.4F(GND4F) J13.5A(GND5A) J13.5D(GND5D) J13.6C(GND6C) J13.6F(GND6F) J13.7A(GND7A) J13.7D(GND7D) J13.8C(GND8C) J13.8F(GND8F) J13.9A(GND9A) J13.9D(GND9D) J13.10C(GND10C) J13.10F(GND10F) J13.11A(GND11A) J13.11D(GND11D) J13.12C(GND12C) J13.12F(GND12F) J13.13D(GND13D) J13.14C(GND14C) J13.14F(GND14F) J13.15A(GND15A) J13.15D(GND15D) J13.16C(GND16C) J13.16F(GND16F) J13.17A(GND17A) J13.17D(GND17D) J13.18C(GND18C) J13.18F(GND18F) J13.19A(GND19A) J13.19D(GND19D) J13.20C(GND20C) J13.20F(GND20F) J13.21A(GND21A) J13.21D(GND21D) J13.22C(GND22C) J13.22F(GND22F) J13.23A(GND23A) J13.23D(GND23D) J13.24C(GND24C) J13.24F(GND24F) J13.25A(GND25A) J13.25D(GND25D) J19.2 J19.10 L5.2 L7.2 R47.2 R50.2 R60.2 R63.2 R67.2 R69.2 R70.2 R79.2 R81.2 R100.1 R101.1 R150.2 R213.2 R219.2 R248.2 R249.2 R275.2 R276.2 R277.2 R280.2 R744.2 R745.2 U8.A1(GND1) U8.A2(GND2) U8.B6(GND3) U8.F1(GND4) U8.F5(GND5) U8.F6(GND6) U8.H1(GND7) U8.H4(~{EN_EXT_SEL}) U11.A1(GND1) U11.A6(GND20) U11.A11(GND47) U11.A16(GND110) U11.A21(GND83) U11.A26(GND69) U11.AA1(GND5) U11.AA11(GND51) U11.AA21(GND81) U11.AA26(GND65) U11.AB8(GND33) U11.AB18(GND91) U11.AC5(GND19) U11.AC15(GND111) U11.AC25(GND70) U11.AD2(GND9) U11.AD12(GND58) U11.AD22(GND77) U11.AE4(GND16) U11.AE9(GND41) U11.AE14(GND119) U11.AE19(GND86) U11.AF1(GND6) U11.AF6(GND23) U11.AF11(GND52) U11.AF16(GND102) U11.AF21(GND80) U11.AF26(GND64) U11.B3(GND10) U11.B8(GND27) U11.B13(GND59) U11.B18(GND95) U11.C5(GND17) U11.C15(GND118) U11.C25(GND72) U11.D2(GND7) U11.D12(GND53) U11.D22(GND79) U11.E9(GND34) U11.E19(GND90) U11.F1(GND2) U11.F6(GND21) U11.F16(GND109) U11.F26(GND68) U11.G3(GND11) U11.G13(GND60) U11.G18(GND94) U11.G23(GND76) U11.H10(GND42) U11.H20(GND85) U11.J7(GND24) U11.J9(GND35) U11.J13(GND61) U11.J15(GND117) U11.J17(GND101) U11.K4(GND14) U11.K8(GND28) U11.K12(GND54) U11.K14(GND123) U11.K16(GND108) U11.K19(GND89) U11.K24(GND74) U11.L1(GND3) U11.L9(GND36) U11.L11(GND48) U11.L13(GND62) U11.L15(GND116) U11.L17(GND100) U11.L21(GND82) U11.L26(GND67) U11.M3(GND12) U11.M8(GND29) U11.M10(GND43) U11.M12(GND55) U11.M13(RSVD2) U11.M14(RSVD1) U11.M16(GND107) U11.M18(GND93) U11.N5(GND18) U11.N9(GND37) U11.N11(GND49) U11.N13(RSVD6) U11.N14(RSVD3) U11.N15(GND115) U11.N17(GND99) U11.N25(GND71) U11.P2(GND8) U11.P7(GND25) U11.P8(GND30) U11.P10(GND44) U11.P12(GND56) U11.P13(RSVD4) U11.P14(RSVD5) U11.P16(GND106) U11.P22(GND78) U11.R9(GND38) U11.R11(GND50) U11.R15(GND114) U11.R17(GND98) U11.R18(RSVD7) U11.R19(GND88) U11.T1(GND4) U11.T6(GND22) U11.T8(GND31) U11.T10(GND45) U11.T12(GND57) U11.T14(GND122) U11.T16(GND105) U11.T18(RSVD8) U11.T26(GND66) U11.U3(GND13) U11.U9(GND39) U11.U13(GND125) U11.U15(GND113) U11.U17(GND97) U11.U18(GND92) U11.U23(GND75) U11.V8(GND32) U11.V10(GND46) U11.V14(GND121) U11.V16(GND104) U11.V20(GND84) U11.W7(GND26) U11.W9(GND40) U11.W13(GND124) U11.W15(GND112) U11.W17(GND96) U11.Y4(GND15) U11.Y14(GND120) U11.Y16(GND103) U11.Y19(GND87) U11.Y24(GND73) U13.1(GND1) U13.7(GND2) U13.14(GND3) U13.20(GND4) U13.41(GND5) U13.46(GND6) U13.53(GND7) U13.55(GND8) U13.60(GND9) U14.1(GND1) U14.7(GND2) U14.14(GND3) U14.20(GND4) U14.41(GND5) U14.46(GND6) U14.53(GND7) U14.55(GND8) U14.60(GND9) U22.3(GND) U24.4(VSS) U28.3(GND) U29.1(DIR2) U29.3(GND) ; also on sheet 4 6 7 8 9 10 16 17 18 19 20 21 22
V5_PWR_FLOAT#: U22.1(A) ; also on sheet 7
VBATT_0: R699.2 U11.K18(VBATT_0)
VCC_1P0V_DDC: C114.1 U11.H15(VCCINT25) U11.J12(VCCINT13) U11.J14(VCCINT21) U11.J16(VCCINT30) U11.K9(VCCINT1) U11.K13(VCCINT18) U11.K15(VCCINT36) U11.L10(VCCINT6) U11.L12(VCCINT14) U11.L14(VCCINT22) U11.L16(VCCINT29) U11.M9(VCCINT2) U11.M11(VCCINT10) U11.M15(VCCINT35) U11.N10(VCCINT7) U11.N12(VCCINT15) U11.N16(VCCINT28) U11.P9(VCCINT3) U11.P11(VCCINT11) U11.P15(VCCINT34) U11.R10(VCCINT8) U11.R12(VCCINT16) U11.R16(VCCINT26) U11.T9(VCCINT4) U11.T11(VCCINT12) U11.T13(VCCINT19) U11.T15(VCCINT33) U11.U10(VCCINT9) U11.U12(VCCINT17) U11.U14(VCCINT23) U11.U16(VCCINT27) U11.V9(VCCINT5) U11.V13(VCCINT20) U11.V15(VCCINT32) U11.W14(VCCINT24) U11.Y15(VCCINT31) ; also on sheet 20
VCC_1P8V: C63.1 C71.1 U8.B1(VCCINT1) U8.E1(VCCINT2) U8.G6(VCCINT3) ; also on sheet 4 6 8 9 19
VCC_2P5V: C74.1 C75.1 C76.1 C83.1 C112.1 C223.1 C224.1 C249.1 C267.1 C270.1 C278.1 C279.1 C292.1 J23.1 R59.1 R64.2 R65.2 R66.2 R68.2 R74.1 R75.1 R95.1 R211.2 R222.2 R255.1 R256.1 R278.1 U11.AA6(VCCO_18_2) U11.AA16(VCCO_2__1) U11.AB3(VCCO_18_3) U11.AB13(VCCO_4_2) U11.AC10(VCCO_4_1) U11.AD7(VCCO_18_1) U11.AD17(VCCO_2_2) U11.B23(VCCO_15_2) U11.C10(VCCO_1_1) U11.C20(VCCO_15_3) U11.D7(VCCO_16_2) U11.D17(VCCO_3__2) U11.E4(VCCO_16_3) U11.E14(VCCO_3_1) U11.E24(VCCO_15_1) U11.F11(VCCO_1_2) U11.F21(VCCO_11_1) U11.G8(VCCO_16_1) U11.H5(VCCO_12__2) U11.H25(VCCO_11_3) U11.J2(VCCO_12__1) U11.J8(VCCAUX11) U11.J22(VCCO_11_2) U11.K17(VCCAUX4) U11.L6(VCCO_12_3) U11.L8(VCCAUX10) U11.M17(VCCAUX3) U11.M23(VCCO_13_2) U11.N8(VCCAUX9) U11.N20(VCCO_13_3) U11.P17(VCCAUX2) U11.R4(VCCO_14_2) U11.R8(VCCAUX8) U11.R24(VCCO_13_1) U11.T17(VCCAUX1) U11.T21(VCCO_17_3) U11.U8(VCCAUX7) U11.V5(VCCO_14_1) U11.V17(VCCAUX12) U11.V25(VCCO_17_1) U11.W2(VCCO_14_3) U11.W8(VCCAUX6) U11.W16(VCCAUX5) U11.W22(VCCO_17_2) U22.5(VCC) U28.1(DIR2) U28.7(VCCA) U28.10(DIR1) ; also on sheet 4 5 6 7 8 10 17 18 19
VCC_3P3V: C55.1 C79.1 C82.1 C146.1 C281.1 C288.1 C293.1 C294.1 FB6.1 FB11.1 J11.1 J24.1 R51.1 R54.1 R56.1 R58.1 R83.1 R85.1 R86.1 R147.2 R266.1 R267.1 R698.1 R699.1 R712.1 U8.B2(VCCO1) U8.C6(VCC02) U8.D6(VCC04) U8.G5(VCC03) U8.H2(VCCJ) U11.W12(VCCO_0_2) U11.Y9(VCCO_0_1) U24.8(VCC) U28.6(VCCB) U29.6(VCCB) U29.7(VCCA) U29.10(DIR1) ; also on sheet 4 5 6 7 8 9 16 17 18 19 21 22
VCC_12V: C235.1 C240.1 FB9.1 FB10.1 ; also on sheet 19
ARSTZ: U11.AC13(IO_L8P_CC_GC_4) ; also on sheet 7
BLKAD_0: U11.E12(IO_L2P_GC_VRN_3) ; also on sheet 7
BLKAD_1: U11.D13(IO_L1P_CC_GC_3) ; also on sheet 7
BLKAD_2: U11.E13(IO_L0N_CC_GC_3) ; also on sheet 7
BLKAD_3: U11.F13(IO_L0N_A18_1) ; also on sheet 7
BLKMD_0: U11.H13(IO_L1N_A16_1) ; also on sheet 6
BLKMD_1: U11.H14(IO_L1P_A17_1) ; also on sheet 6
CLKIN_R: U11.AD13(IO_L6P_GC_4) ; also on sheet 7
COMP_DATA: U11.G19(IO_L8P_CC_A3_D19_1) ; also on sheet 6
CS_B_0: R79.1 R268.1 U11.N18(CS_B_0)
DAD_A_ADDR0: U11.E1(IO_L0N_14) U13.19(ADDR0)
DAD_A_ADDR1: U11.E2(IO_L0P_14) U13.18(ADDR1)
DAD_A_ADDR2: U11.E3(IO_L1N_14) U13.17(ADDR2)
DAD_A_ADDR3: U11.F3(IO_L1P_14) U13.16(ADDR3)
DAD_A_MODE0: U13.3(MODE0) ; also on sheet 10
DAD_A_MODE1: U13.2(MODE1) ; also on sheet 10
DAD_A_SCPENZ: U11.AE3(IO_L16N_18) U13.58(\\~{SCPENZ})
DAD_A_SEL0: U11.AB12(IO_L7P_GC_VRN_4) U13.5(SEL0)
DAD_A_SEL1: U11.AC12(IO_L8N_CC_GC_4) U13.4(SEL1)
DAD_A_STROBE: U11.AF3(IO_L16P_18) U13.15(STROBE)
DAD_B_ADDR0: U11.E26(IO_L1N_13) U14.19(ADDR0)
DAD_B_ADDR1: U11.E25(IO_L1P_13) U14.18(ADDR1)
DAD_B_ADDR2: U11.F25(IO_L0N_13) U14.17(ADDR2)
DAD_B_ADDR3: U11.F24(IO_L0P_13) U14.16(ADDR3)
DAD_B_MODE0: U14.3(MODE0) ; also on sheet 10
DAD_B_MODE1: U14.2(MODE1) ; also on sheet 10
DAD_B_SCPENZ: U11.AB19(IO_L18N_17) U14.58(\\~{SCPENZ})
DAD_B_SEL0: U14.5(SEL0) ; also on sheet 10
DAD_B_SEL1: U14.4(SEL1) ; also on sheet 10
DAD_B_STROBE: U11.AB20(IO_L18P_17) U14.15(STROBE)
DAD_INIT: R63.1 R66.1 R67.1 R68.1 U11.AF4(IO_L18N_18) U13.59(\~{RESET}) U14.59(\~{RESET})
DAD_OEZ: J10.1 R255.2 U11.AF5(IO_L18P_18) U13.6(\\~{OEZ})
DDC_DCLKOUT_A_DPN: J13.5C(DCLKAN) U11.N1(IO_L8N_CC_14)
DDC_DCLKOUT_A_DPP: J13.5B(DCLKAP) U11.M1(IO_L8P_CC_14)
DDC_DCLKOUT_B_DPN: J13.21C(DCLKBN) U11.Y5(IO_L8N_CC_18)
DDC_DCLKOUT_B_DPP: J13.21B(DCLKBP) U11.Y6(IO_L8P_CC_18)
DDC_DCLKOUT_C_DPN: U11.AA22(IO_L10N_CC_17) ; also on sheet 16
DDC_DCLKOUT_C_DPP: U11.AB22(IO_L10P_CC_17) ; also on sheet 16
DDC_DCLKOUT_D_DPN: U11.M26(IO_L8N_CC_13) ; also on sheet 16
DDC_DCLKOUT_D_DPP: U11.M25(IO_L8P_CC_13) ; also on sheet 16
DDC_DOUT_A0_DPN: J13.10E(DDAN0) U11.AE2(IO_L19N_14)
DDC_DOUT_A0_DPP: J13.10D(DDAP0) U11.AF2(IO_L19P_14)
DDC_DOUT_A1_DPN: J13.9C(DDAN1) U11.AD1(IO_L18N_14)
DDC_DOUT_A1_DPP: J13.9B(DDAP1) U11.AE1(IO_L18P_14)
DDC_DOUT_A2_DPN: J13.9F(DDAN2) U11.AC1(IO_L17N_14)
DDC_DOUT_A2_DPP: J13.9E(DDAP2) U11.AC2(IO_L17P_14)
DDC_DOUT_A3_DPN: J13.8B(DDAN3) U11.AB1(IO_L16N_14)
DDC_DOUT_A3_DPP: J13.8A(DDAP3) U11.AB2(IO_L16P_14)
DDC_DOUT_A4_DPN: J13.8E(DDAN4) U11.Y2(IO_L15N_14)
DDC_DOUT_A4_DPP: J13.8D(DDAP4) U11.AA2(IO_L15P_14)
DDC_DOUT_A5_DPN: J13.7C(DDAN5) U11.W1(IO_L14N_VREF_14)
DDC_DOUT_A5_DPP: J13.7B(DDAP5) U11.Y1(IO_L14P_14)
DDC_DOUT_A6_DPN: J13.7F(DDAN6) U11.V1(IO_L13N_14)
DDC_DOUT_A6_DPP: J13.7E(DDAP6) U11.V2(IO_L13P_14)
DDC_DOUT_A7_DPN: J13.6B(DDAN7) U11.U1(IO_L12N_VRP_14)
DDC_DOUT_A7_DPP: J13.6A(DDAP7) U11.U2(IO_L12P_VRN_14)
DDC_DOUT_A8_DPN: J13.5F(DDAN8) U11.R2(IO_L11N_CC_14)
DDC_DOUT_A8_DPP: J13.5E(DDAP8) U11.T2(IO_L11P_CC_14)
DDC_DOUT_A9_DPN: J13.4B(DDAN9) U11.N2(IO_L9N_CC_14)
DDC_DOUT_A9_DPP: J13.4A(DDAP9) U11.M2(IO_L9P_CC_14)
DDC_DOUT_A10_DPN: J13.4E(DDAN10) U11.K1(IO_L6N_14)
DDC_DOUT_A10_DPP: J13.4D(DDAP10) U11.L2(IO_L6P_14)
DDC_DOUT_A11_DPN: J13.3C(DDAN11) U11.K2(IO_L4N_VREF_14)
DDC_DOUT_A11_DPP: J13.3B(DDAP11) U11.K3(IO_L4P_14)
DDC_DOUT_A12_DPN: J13.3F(DDAN12) U11.J3(IO_L5N_14)
DDC_DOUT_A12_DPP: J13.3E(DDAP12) U11.H3(IO_L5P_14)
DDC_DOUT_A13_DPN: J13.2B(DDAN13) U11.H2(IO_L7N_14)
DDC_DOUT_A13_DPP: J13.2A(DDAP13) U11.J1(IO_L7P_14)
DDC_DOUT_A14_DPN: J13.2E(DDAN14) U11.H1(IO_L2N_14)
DDC_DOUT_A14_DPP: J13.2D(DDAP14) U11.G1(IO_L2P_14)
DDC_DOUT_A15_DPN: J13.1F(DDAN15) U11.G2(IO_L3N_14)
DDC_DOUT_A15_DPP: J13.1E(DDAP15) U11.F2(IO_L3P_14)
DDC_DOUT_B0_DPN: J13.16E(DDBN0) U11.AE5(IO_L19N_18)
DDC_DOUT_B0_DPP: J13.16D(DDBP0) U11.AE6(IO_L19P_18)
DDC_DOUT_B1_DPN: J13.17C(DDBN1) U11.AD3(IO_L13N_18)
DDC_DOUT_B1_DPP: J13.17B(DDBP1) U11.AD4(IO_L13P_18)
DDC_DOUT_B2_DPN: J13.17F(DDBN2) U11.AD5(IO_L17N_18)
DDC_DOUT_B2_DPP: J13.17E(DDBP2) U11.AD6(IO_L17P_18)
DDC_DOUT_B3_DPN: J13.18B(DDBN3) U11.AC3(IO_L12N_VRP_18)
DDC_DOUT_B3_DPP: J13.18A(DDBP3) U11.AC4(IO_L12P_VRN_18)
DDC_DOUT_B4_DPN: J13.18E(DDBN4) U11.AB5(IO_L14N_VREF_18)
DDC_DOUT_B4_DPP: J13.18D(DDBP4) U11.AB6(IO_L14P_18)
DDC_DOUT_B5_DPN: J13.19C(DDBN5) U11.AB7(IO_L15N_18)
DDC_DOUT_B5_DPP: J13.19B(DDBP5) U11.AC6(IO_L15P_18)
DDC_DOUT_B6_DPN: J13.19F(DDBN6) U11.AA5(IO_L9N_CC_18)
DDC_DOUT_B6_DPP: J13.19E(DDBP6) U11.AA4(IO_L9P_CC_18)
DDC_DOUT_B7_DPN: J13.20B(DDBN7) U11.AA7(IO_L10N_CC_18)
DDC_DOUT_B7_DPP: J13.20A(DDBP7) U11.Y7(IO_L10P_CC_18)
DDC_DOUT_B8_DPN: J13.21F(DDBN8) U11.Y3(IO_L5N_18)
DDC_DOUT_B8_DPP: J13.21E(DDBP8) U11.W3(IO_L5P_18)
DDC_DOUT_B9_DPN: J13.22B(DDBN9) U11.W4(IO_L4N_VREF_18)
DDC_DOUT_B9_DPP: J13.22A(DDBP9) U11.V4(IO_L4P_18)
DDC_DOUT_B10_DPN: J13.22E(DDBN10) U11.W6(IO_L7N_18)
DDC_DOUT_B10_DPP: J13.22D(DDBP10) U11.W5(IO_L7P_18)
DDC_DOUT_B11_DPN: J13.23C(DDBN11) U11.V7(IO_L6N_18)
DDC_DOUT_B11_DPP: J13.23B(DDBP11) U11.V6(IO_L6P_18)
DDC_DOUT_B12_DPN: J13.23F(DDBN12) U11.U4(IO_L0N_18)
DDC_DOUT_B12_DPP: J13.23E(DDBP12) U11.V3(IO_L0P_18)
DDC_DOUT_B13_DPN: J13.24B(DDBN13) U11.T4(IO_L1N_18)
DDC_DOUT_B13_DPP: J13.24A(DDBP13) U11.T5(IO_L1P_18)
DDC_DOUT_B14_DPN: J13.24E(DDBN14) U11.U6(IO_L3N_18)
DDC_DOUT_B14_DPP: J13.24D(DDBP14) U11.U5(IO_L3P_18)
DDC_DOUT_B15_DPN: J13.25C(DDBN15) U11.U7(IO_L2N_18)
DDC_DOUT_B15_DPP: J13.25B(DDBP15) U11.T7(IO_L2P_18)
DDC_DOUT_C0_DPN: U11.T22(IO_L0N_17) ; also on sheet 16
DDC_DOUT_C0_DPP: U11.T23(IO_L0P_17) ; also on sheet 16
DDC_DOUT_C1_DPN: U11.R20(IO_L1N_17) ; also on sheet 16
DDC_DOUT_C1_DPP: U11.R21(IO_L1P_17) ; also on sheet 16
DDC_DOUT_C2_DPN: U11.T19(IO_L2N_17) ; also on sheet 16
DDC_DOUT_C2_DPP: U11.T20(IO_L2P_17) ; also on sheet 16
DDC_DOUT_C3_DPN: U11.U21(IO_L3N_17) ; also on sheet 16
DDC_DOUT_C3_DPP: U11.U22(IO_L3P_17) ; also on sheet 16
DDC_DOUT_C4_DPN: U11.U20(IO_L14N_VREF_17) ; also on sheet 16
DDC_DOUT_C4_DPP: U11.U19(IO_L14P_17) ; also on sheet 16
DDC_DOUT_C5_DPN: U11.V23(IO_L5N_17) ; also on sheet 16
DDC_DOUT_C5_DPP: U11.V24(IO_L5P_17) ; also on sheet 16
DDC_DOUT_C6_DPN: U11.V22(IO_L12N_VRP_17) ; also on sheet 16
DDC_DOUT_C6_DPP: U11.V21(IO_L12P_VRN_17) ; also on sheet 16
DDC_DOUT_C7_DPN: U11.W19(IO_L15N_17) ; also on sheet 16
DDC_DOUT_C7_DPP: U11.V19(IO_L15P_17) ; also on sheet 16
DDC_DOUT_C8_DPN: U11.W23(IO_L4N_VREF_17) ; also on sheet 16
DDC_DOUT_C8_DPP: U11.W24(IO_L4P_17) ; also on sheet 16
DDC_DOUT_C9_DPN: U11.Y22(IO_L7N_17) ; also on sheet 16
DDC_DOUT_C9_DPP: U11.Y23(IO_L7P_17) ; also on sheet 16
DDC_DOUT_C10_DPN: U11.Y20(IO_L16N_17) ; also on sheet 16
DDC_DOUT_C10_DPP: U11.Y21(IO_L16P_17) ; also on sheet 16
DDC_DOUT_C11_DPN: U11.AA24(IO_L6N_17) ; also on sheet 16
DDC_DOUT_C11_DPP: U11.AA23(IO_L6P_17) ; also on sheet 16
DDC_DOUT_C12_DPN: U11.AA19(IO_L19N_17) ; also on sheet 16
DDC_DOUT_C12_DPP: U11.AA20(IO_L19P_17) ; also on sheet 16
DDC_DOUT_C13_DPN: U11.AC24(IO_L9N_CC_17) ; also on sheet 16
DDC_DOUT_C13_DPP: U11.AB24(IO_L9P_CC_17) ; also on sheet 16
DDC_DOUT_C14_DPN: U11.AC19(IO_L17N_17) ; also on sheet 16
DDC_DOUT_C14_DPP: U11.AD19(IO_L17P_17) ; also on sheet 16
DDC_DOUT_C15_DPN: U11.AC22(IO_L8N_CC_17) ; also on sheet 16
DDC_DOUT_C15_DPP: U11.AC23(IO_L8P_CC_17) ; also on sheet 16
DDC_DOUT_D0_DPN: U11.AB26(IO_L19N_13) ; also on sheet 16
DDC_DOUT_D0_DPP: U11.AC26(IO_L19P_13) ; also on sheet 16
DDC_DOUT_D1_DPN: U11.AA25(IO_L18N_13) ; also on sheet 16
DDC_DOUT_D1_DPP: U11.AB25(IO_L18P_13) ; also on sheet 16
DDC_DOUT_D2_DPN: U11.Y26(IO_L17N_13) ; also on sheet 16
DDC_DOUT_D2_DPP: U11.Y25(IO_L17P_13) ; also on sheet 16
DDC_DOUT_D3_DPN: U11.W26(IO_L16N_13) ; also on sheet 16
DDC_DOUT_D3_DPP: U11.W25(IO_L16P_13) ; also on sheet 16
DDC_DOUT_D4_DPN: U11.U26(IO_L14N_VREF_13) ; also on sheet 16
DDC_DOUT_D4_DPP: U11.V26(IO_L14P_13) ; also on sheet 16
DDC_DOUT_D5_DPN: U11.U25(IO_L15N_13) ; also on sheet 16
DDC_DOUT_D5_DPP: U11.U24(IO_L15P_13) ; also on sheet 16
DDC_DOUT_D6_DPN: U11.T25(IO_L13N_13) ; also on sheet 16
DDC_DOUT_D6_DPP: U11.T24(IO_L13P_13) ; also on sheet 16
DDC_DOUT_D7_DPN: U11.R26(IO_L12N_VRP_13) ; also on sheet 16
DDC_DOUT_D7_DPP: U11.R25(IO_L12P_VRN_13) ; also on sheet 16
DDC_DOUT_D8_DPN: U11.P24(IO_L11N_CC_13) ; also on sheet 16
DDC_DOUT_D8_DPP: U11.P25(IO_L11P_CC_13) ; also on sheet 16
DDC_DOUT_D9_DPN: U11.N24(IO_L9N_CC_13) ; also on sheet 16
DDC_DOUT_D9_DPP: U11.M24(IO_L9P_CC_13) ; also on sheet 16
DDC_DOUT_D10_DPN: U11.L25(IO_L6N_13) ; also on sheet 16
DDC_DOUT_D10_DPP: U11.L24(IO_L6P_13) ; also on sheet 16
DDC_DOUT_D11_DPN: U11.K26(IO_L7N_13) ; also on sheet 16
DDC_DOUT_D11_DPP: U11.K25(IO_L7P_13) ; also on sheet 16
DDC_DOUT_D12_DPN: U11.J26(IO_L4N_VREF_13) ; also on sheet 16
DDC_DOUT_D12_DPP: U11.J25(IO_L4P_13) ; also on sheet 16
DDC_DOUT_D13_DPN: U11.J24(IO_L5N_13) ; also on sheet 16
DDC_DOUT_D13_DPP: U11.H24(IO_L5P_13) ; also on sheet 16
DDC_DOUT_D14_DPN: U11.H26(IO_L2N_13) ; also on sheet 16
DDC_DOUT_D14_DPP: U11.G26(IO_L2P_13) ; also on sheet 16
DDC_DOUT_D15_DPN: U11.G25(IO_L3N_13) ; also on sheet 16
DDC_DOUT_D15_DPP: U11.G24(IO_L3P_13) ; also on sheet 16
DDC_M0: R83.2 R275.1 U11.W18(M0_0)
DDC_M1: R85.2 R276.1 U11.Y17(M1_0)
DDC_M2: R86.2 R277.1 U11.V18(M2_0)
DDC_SCTRL_AN: J13.6E(SCTRLAN) U11.R1(IO_L10N_CC_14)
DDC_SCTRL_AP: J13.6D(SCTRLAP) U11.P1(IO_L10P_CC_14)
DDC_SCTRL_BN: J13.20E(SCTRLBN) U11.AA3(IO_L11N_CC_18)
DDC_SCTRL_BP: J13.20D(SCTRLBP) U11.AB4(IO_L11P_CC_18)
DDC_SCTRL_CN: U11.W20(IO_L13N_17) ; also on sheet 16
DDC_SCTRL_CP: U11.W21(IO_L13P_17) ; also on sheet 16
DDC_SCTRL_DN: U11.N26(IO_L10N_CC_13) ; also on sheet 16
DDC_SCTRL_DP: U11.P26(IO_L10P_CC_13) ; also on sheet 16
DDC_SPARE_0: U11.AB21(IO_L11N_CC_17) ; also on sheet 6
DDC_SPARE_1: U11.AC21(IO_L11P_CC_17) ; also on sheet 6
DDC_VERSION_0: U11.F18(IO_L9P_GC_3) ; also on sheet 7
DDC_VERSION_1: U11.G17(IO_L6N_A6_D22_1) ; also on sheet 7
DDC_VERSION_2: U11.H18(IO_L8N_CC_A2_D18_1) ; also on sheet 7
DLPC_CFG_CCLK: R50.1 R56.2 R272.1 R273.1 U11.J10(CCLK_0)
DLPC_CFG_CSZ: R274.1 R282.2
DLPC_CFG_DIN: R270.1 R271.1 U11.K11(D_IN_0)
DLPC_CFG_DOUT: R269.1 R281.2
DMD_A_RESET: R94.1 U11.AD14(IO_L4N_GC_VREF_4)
DMD_A_RESET_FILT: C126.1 J13.11F(DMDRSTZ) R94.2
DMD_A_SCPCLK_FILT: C137.1 J13.10B(SCPCLK) R105.2
DMD_A_SCPDO_FILT: C128.1 J13.10A(SCPD0) R96.2
DMD_A_SCPENZ: R98.1 U11.AB14(IO_L7N_D4_2)
DMD_A_SCPENZ_FILT: C132.1 J13.11C(DMDSELZ) R98.2
DMD_B_RESET: U11.AA12(IO_L8P_D3_2) ; also on sheet 16
DMD_B_SCPENZ: U11.AC14(IO_L6N_GC_4) ; also on sheet 16
DMD_TYPE_0: U11.AA17(IO_L3P_A21_2) ; also on sheet 6
DMD_TYPE_1: U11.AC16(IO_L2N_GC_D10_4) ; also on sheet 6
DMD_TYPE_2: U11.AB17(IO_L3N_A20_2) ; also on sheet 6
DMD_TYPE_3: U11.AD15(IO_L4P_GC_4) ; also on sheet 6
DMDSPARE0: J13.12D(DMDSPARE0) R100.2 TP27.1(TP)
DMDSPARE1: J13.11B(DMDSPARE1) R101.2 TP30.1(TP)
DONE_DDC: D3.2(CATHODE) R54.2 R710.2 U11.K10(DONE_0)
DONE_DDC_PROM: R710.1 U8.B4(~{CE})
DXN_0: TP17.1(TP) U11.R13(DXN_0)
DXP_0: TP14.1(TP) U11.R14(DXP_0)
ECP2_FINISHED: D17.1(ANODE) U11.Y18(IO_L1N_CC_A24_2)
ECP2_M_TP0: U11.AD11(IO_L9P_CC_GC_4) ; also on sheet 21
ECP2_M_TP1: U11.AD10(IO_L9N_CC_GC_4) ; also on sheet 21
ECP2_M_TP2: U11.AD8(IO_L5P_GC_4) ; also on sheet 21
ECP2_M_TP3: U11.AC8(IO_L3P_GC_D9_4) ; also on sheet 21
ECP2_M_TP4: U11.AC7(IO_L5N_GC_4) ; also on sheet 21
ECP2_M_TP5: U11.AC9(IO_L3N_GC_D8_4) ; also on sheet 21
ECP2_M_TP6: U11.AB9(IO_L1N_GC_D12_4) ; also on sheet 21
ECP2_M_TP7: U11.AA8(IO_L2N_A22_2) ; also on sheet 21
ECP2_M_TP8: R281.1 U11.AA9(IO_L4N_VREF_FOE_B_MOSI_2) ; also on sheet 21
ECP2_M_TP9: U11.Y8(IO_L2P_A23_2) ; also on sheet 21
ECP2_M_TP10: U11.AB10(IO_L1P_GC_D13_4) ; also on sheet 21
ECP2_M_TP11: R282.1 U11.AA10(IO_L4P_FCS_B_2) ; also on sheet 21
ECP2_M_TP12: U11.Y10(IO_L0P_CC_RS1_2) ; also on sheet 21
ECP2_M_TP13: U11.AC11(IO_L7N_GC_VRP_4) ; also on sheet 21
ECP2_M_TP14: U11.Y12(IO_L6P_D7_2) ; also on sheet 21
ECP2_M_TP15: U11.Y11(IO_L0N_CC_RS0_2) ; also on sheet 21
ECP2_M_TP16: R278.2 U11.AB11(IO_L8N_D2_FS2_2) ; also on sheet 21
ECP2_M_TP17: U11.H8(IO_L9N_CC_A0_D16_1) ; also on sheet 21
ECP2_M_TP18: U11.H9(IO_L9P_CC_A1_D17_1) ; also on sheet 21
ECP2_M_TP19: U11.F12(IO_L2N_GC_VRP_3) ; also on sheet 21
ECP2_M_TP20: U11.G11(IO_L5N_A8_D24_1) ; also on sheet 21
ECP2_M_TP21: U11.G12(IO_L3P_A13_D29_1) ; also on sheet 21
ECP2_M_TP22: U11.E11(IO_L4N_GC_VREF_3) ; also on sheet 21
ECP2_M_TP23: U11.E10(IO_L4P_GC_3) ; also on sheet 21
ECP2_M_TP24: U11.E8(IO_L8N_GC_3) ; also on sheet 21
ECP2_M_TP25: U11.F10(IO_L6N_GC_3) ; also on sheet 21
ECP2_M_TP26: U11.F9(IO_L6P_GC_3) ; also on sheet 21
ECP2_M_TP27: U11.F8(IO_L8P_GC_3) ; also on sheet 21
ECP2_M_TP28: U11.G10(IO_L7P_A5_D21_1) ; also on sheet 21
ECP2_M_TP29: U11.G9(IO_L7N_A4_D20_1) ; also on sheet 21
ECP2_M_TP30: U11.H11(IO_L5P_A9_D25_1) ; also on sheet 21
ECP2_M_TP31: U11.H12(IO_L3N_A12_D28_1) ; also on sheet 21
FLASH_CFG_CCLK: R272.2 U29.8(A1)
FLASH_CFG_CCLK_F: R693.1 U24.6(SCK) U29.5(B1)
FLASH_CFG_CSZ: R268.2 R274.2 U28.8(A1)
FLASH_CFG_CSZ_F: R691.1 R694.1 R712.2 U24.1(CS#) U28.5(B1)
FLASH_CFG_DIN: R269.2 U28.9(A2)
FLASH_CFG_DIN_F: R692.2 U24.5(SI/IO0) U28.4(B2)
FLASH_CFG_DOUT: R270.2 U29.9(A2)
FLASH_CFG_DOUT_F: R695.1 U24.2(SO/IO1) U29.4(B2)
HSWAPEN: R698.2 U11.L18(HSWAPEN_0)
INIT_ACTIVE: U11.AA18(IO_L1P_CC_A25_2) ; also on sheet 7
INTB_DDC: R58.2 R711.2 U11.J11(INIT_B_0)
INTB_DDC_PROM: R711.1 U8.A3(OE/~{RESET})
MBRST1_0: J13.14D(MBRST0) RN4.9 TP28.1(TP)
MBRST1_1: J13.13C(MBRST1) RN4.10(9)
MBRST1_2: J13.15E(MBRST2) RN4.11(9)
MBRST1_3: J13.14E(MBRST3) RN4.12(9)
MBRST1_4: J13.13F(MBRST4) RN4.13(9)
MBRST1_5: J13.13E(MBRST5) RN4.14(9)
MBRST1_6: J13.14B(MBRST6) RN4.15(9)
MBRST1_7: J13.15C(MBRST7) RN4.16(9)
MBRST1_8: J13.15F(MBRST8) RN3.9 TP11.1(TP)
MBRST1_9: J13.15B(MBRST9) RN3.10(9)
MBRST1_10: J13.14A(MBRST10) RN3.11(9)
MBRST1_11: J13.12E(MBRST11) RN3.12(9)
MBRST1_12: J13.16B(MBRST12) RN3.13(9)
MBRST1_13: J13.16A(MBRST13) RN3.14(9)
MBRST1_14: J13.12B(MBRST14) RN3.15(9)
MBRST1_15: J13.12A(MBRST15) RN3.16(9)
MBRST2_0: RN2.9 TP16.1(TP) ; also on sheet 16
MBRST2_1: RN2.10(9) ; also on sheet 16
MBRST2_2: RN2.11(9) ; also on sheet 16
MBRST2_3: RN2.12(9) ; also on sheet 16
MBRST2_4: RN2.13(9) ; also on sheet 16
MBRST2_5: RN2.14(9) ; also on sheet 16
MBRST2_6: RN2.15(9) ; also on sheet 16
MBRST2_7: RN2.16(9) ; also on sheet 16
MBRST2_8: RN1.9 TP20.1(TP) ; also on sheet 16
MBRST2_9: RN1.10(9) ; also on sheet 16
MBRST2_10: RN1.11(9) ; also on sheet 16
MBRST2_11: RN1.12(9) ; also on sheet 16
MBRST2_12: RN1.13(9) ; also on sheet 16
MBRST2_13: RN1.14(9) ; also on sheet 16
MBRST2_14: RN1.15(9) ; also on sheet 16
MBRST2_15: RN1.16(9) ; also on sheet 16
NS_FLIP: U11.F19(IO_L7N_GC_3) ; also on sheet 7
PROGB_DDC: R51.2 U8.D1(~{CF}) U11.J18(PROGRAM_B_0)
PROM_CCK_DDC: R49.1 R53.1 R273.2
PROM_D0_DDC: R271.2 U8.H6(D0)
PWR_FLOAT: U11.AC17(IO_L2P_GC_D11_4) U22.4(Y)
PWRGD: U22.2(B) ; also on sheet 19
RDWR_B: R81.1 U11.P18(RDWR_B_0)
ROWAD_0: U11.D14(IO_L1N_CC_GC_3) ; also on sheet 7
ROWAD_1: U11.D15(IO_L3P_GC_3) ; also on sheet 7
ROWAD_2: U11.E15(IO_L3N_GC_3) ; also on sheet 7
ROWAD_3: U11.F14(IO_L0P_CC_GC_3) ; also on sheet 7
ROWAD_4: U11.G14(IO_L0P_A19_1) ; also on sheet 7
ROWAD_5: U11.E16(IO_L5P_GC_3) ; also on sheet 7
ROWAD_6: U11.F15(IO_L2P_A15_D31_1) ; also on sheet 7
ROWAD_7: U11.G15(IO_L2N_A14_D30_1) ; also on sheet 7
ROWAD_8: U11.E17(IO_L5N_GC_3) ; also on sheet 7
ROWAD_9: U11.F17(IO_L9N_GC_3) ; also on sheet 7
ROWAD_10: U11.G16(IO_L4P_A11_D27_1) ; also on sheet 7
ROWMD_0: U11.H17(IO_L6P_A7_D23_1) ; also on sheet 6
ROWMD_1: U11.H16(IO_L4N_VREF_A10_D26_1) ; also on sheet 6
RST2BLKZ: U11.E18(IO_L7P_GC_3) ; also on sheet 6
RST_ACTIVE: U11.AB16(IO_L5N_CSO_B_2) ; also on sheet 7
SCPCLK: R105.1 TP31.1(TP) U11.AB15(IO_L5P_FWE_B_2) U13.56(SCPCK) U14.56(SCPCK) ; also on sheet 16
SCPDI: J13.11E(SCP0_DI) R256.2 TP18.1(TP) U11.AA15(IO_L7P_D5_2) U13.42(SCPDO) U14.42(SCPDO) ; also on sheet 16
SCPDO: R95.2 R96.1 TP7.1(TP) U11.AA14(IO_L9N_D0_FS0_2) U13.57(SCPDI) U14.57(SCPDI) ; also on sheet 16
STEPVCC: U11.Y13(IO_L6N_D6_2) ; also on sheet 6
TCK_JTAG: U8.H3(TCK) U11.U11(TCK_0) ; also on sheet 8
TDI_DDC: R736.2 U8.G1(TDI) ; also on sheet 8
TDO_DDC: U11.W10(TDO_0) ; also on sheet 8
TDO_XCF16DDC: R736.1 U8.E6(TDO) U11.V11(TDI_0)
TMS_JTAG: U8.E2(TMS) U11.V12(TMS_0) ; also on sheet 8
U28_EN: J23.2 R744.1 U28.2(\\~{OE})
U29_EN: J24.2 R745.1 U29.2(\\~{OE})
VBIAS: C101.1 C108.1 R92.1 U13.21(VBIAS_RAIL0) U13.30(VBIAS_RAIL1) U13.31(VBIAS_RAIL2) U13.40(VBIAS_RAIL3) U13.61(VBIAS_RAIL4) U13.70(VBIAS_RAIL5) U13.71(VBIAS_RAIL6) U13.80(VBIAS_RAIL7)
VBIAS_2: C102.1 C107.1 R90.1 U14.21(VBIAS_RAIL0) U14.30(VBIAS_RAIL1) U14.31(VBIAS_RAIL2) U14.40(VBIAS_RAIL3) U14.61(VBIAS_RAIL4) U14.70(VBIAS_RAIL5) U14.71(VBIAS_RAIL6) U14.80(VBIAS_RAIL7)
VLED0: U11.AC18(IO_L0N_GC_D14_4) ; also on sheet 4
VLED1: U11.AD18(IO_L0P_GC_D15_4) ; also on sheet 4
VOFF_1: C121.1 D8.2(CATHODE) FB3.1 R214.2
VOFF_2: R233.2 ; also on sheet 16
VRST: C263.1 C266.1 R88.2 U13.25(VRST_RAIL0) U13.26(VRST_RAIL1) U13.35(VRST_RAIL2) U13.36(VRST_RAIL3) U13.65(VRST_RAIL4) U13.66(VRST_RAIL5) U13.75(VRST_RAIL6) U13.76(VRST_RAIL7) U13.81(THPAD)
VRST_2: C105.1 C106.1 R89.2 U14.25(VRST_RAIL0) U14.26(VRST_RAIL1) U14.35(VRST_RAIL2) U14.36(VRST_RAIL3) U14.65(VRST_RAIL4) U14.66(VRST_RAIL5) U14.75(VRST_RAIL6) U14.76(VRST_RAIL7) U14.81(THPAD)
WDT_ENBLZ: R280.1 U11.AA13(IO_L9P_D1_FS1_2) ; also on sheet 6
N17881342: RN1.8 U14.62(OUT08)
N17881344: R211.1 R219.1 U14.44(DEV_ID0)
N17881394: C109.1 C124.1 D7.2(CATHODE) R90.2 U14.9(VBIAS)
N17881419: C113.1 C122.1 L4.2 U14.10(VBIAS_LHI)
N17881437: D7.1(ANODE) L4.1 U14.8(VBIAS_SWL)
N17881507: C247.1 C257.1 C265.1 R233.1 R249.1 U14.23(VOFF_RAIL0) U14.28(VOFF_RAIL1) U14.33(VOFF_RAIL2) U14.38(VOFF_RAIL3) U14.49(VOFF) U14.63(VOFF_RAIL4) U14.68(VOFF_RAIL5) U14.73(VOFF_RAIL6) U14.78(VOFF_RAIL7)
N17881569: R74.2 TP13.1(TP) U14.43(\~{IRQZ})
N17881571: RN2.1(8) U14.39(OUT07)
N17881603: RN2.2(8) U14.37(OUT06)
N17881627: R213.1 R222.1 U14.45(DEV_ID1)
N17881647: J10.2 R59.2 U14.6(\\~{OEZ})
N17881654: RN2.3(8) U14.34(OUT05)
N17881962: RN1.1(8) U14.79(OUT15)
N17881976: RN2.4(8) U14.32(OUT04)
N17881998: C116.2 C125.1 D4.1(ANODE) R89.1 U14.13(VRST)
N17882046: D4.2(CATHODE) L7.1 U14.12(VRST_SWL)
N17882150: RN1.2(8) U14.77(OUT14)
N17882156: RN2.5(8) U14.29(OUT03)
N17882179: C237.1 C241.1 C246.1 C256.1 FB9.2 U14.11(V12_1) U14.48(V12_2) U14.50(V12_3)
N17882240: C87.1 C89.1 U14.47(V5REG)
N17882311: RN1.3(8) U14.74(OUT13)
N17882322: RN2.6(8) U14.27(OUT02)
N17882382: RN1.4(8) U14.72(OUT12)
N17882388: RN2.7(8) U14.24(OUT01)
N17882433: RN1.5(8) U14.69(OUT11)
N17882443: RN2.8 U14.22(OUT00)
N17882524: RN1.6(8) U14.67(OUT10)
N17882575: RN1.7(8) U14.64(OUT09)
N20172057: RN3.1(8) U13.79(OUT15)
N20173243: RN3.2(8) U13.77(OUT14)
N20174431: RN3.3(8) U13.74(OUT13)
N20175621: RN3.4(8) U13.72(OUT12)
N20176813: RN3.5(8) U13.69(OUT11)
N20178007: RN3.6(8) U13.67(OUT10)
N20179203: RN3.7(8) U13.64(OUT09)
N20180401: RN3.8 U13.62(OUT08)
N20181601: RN4.1(8) U13.39(OUT07)
N20182803: RN4.2(8) U13.37(OUT06)
N20184007: RN4.3(8) U13.34(OUT05)
N20185213: RN4.4(8) U13.32(OUT04)
N20186421: RN4.5(8) U13.29(OUT03)
N20187631: RN4.6(8) U13.27(OUT02)
N20188843: RN4.7(8) U13.24(OUT01)
N20190057: RN4.8 U13.22(OUT00)
N20219307: R65.1 R70.1 U13.44(DEV_ID0)
N20224230: R64.1 R69.1 U13.45(DEV_ID1)
N20316396: C250.1 C251.1 C252.1 C254.1 FB10.2 U13.11(V12_1) U13.48(V12_2) U13.50(V12_3)
N20316449: C231.1 C232.1 U13.47(V5REG)
N20340815: C111.1 C119.2 D5.1(ANODE) R88.1 U13.13(VRST)
N20340851: D5.2(CATHODE) L5.1 U13.12(VRST_SWL)
N20362233: C120.1 C130.1 D6.2(CATHODE) R92.2 U13.9(VBIAS)
N20362247: C104.1 C110.1 L6.2 U13.10(VBIAS_LHI)
N20362278: D6.1(ANODE) L6.1 U13.8(VBIAS_SWL)
N20378881: C238.1 C245.1 C253.1 R214.1 R248.1 U13.23(VOFF_RAIL0) U13.28(VOFF_RAIL1) U13.33(VOFF_RAIL2) U13.38(VOFF_RAIL3) U13.49(VOFF) U13.63(VOFF_RAIL4) U13.68(VOFF_RAIL5) U13.73(VOFF_RAIL6) U13.78(VOFF_RAIL7)
N20410950: R75.2 TP12.1(TP) U13.43(\~{IRQZ})
N20628237: C150.1 FB6.2 J13.1B(DMD3P3VA0) J13.1C(DMD3P3VA1)
N20672663: C131.1 FB3.2 J13.13A(DMDVCC2_0) J13.13B(DMDVCC2)
N20672701: C282.1 FB11.2 J13.25E(DMD3P3VB1) J13.25F(DMD3P3VB0)
N25461313: D3.1(ANODE) R147.1
N25461323: D17.2(CATHODE) R150.1
N53661741: R53.2 U8.C2(CLKOUT)
N53662038: R49.2 U8.B3(CLK)
N56121568: J11.2 R60.1 U8.G3(REV_SEL0)
N56121574: R47.1 U8.G4(REV_SEL1)
N62215795: R266.2 U24.7(IO3/RESET#)
N62215800: R267.2 U24.3(WP#/IO2)
N62298106: J19.1 R691.2
N62298121: J19.4 TP197.1
N62298123: J19.3 TP196.1
N62298130: J19.6 TP198.1
N62298151: J19.8 R692.1
N62298153: J19.7 R693.2
N62298170: J19.9 R694.2
N62299173: J19.5 R695.2

Not connected (* = marked no-connect by the designer): U8 A4(DNC1)* A5(D6)* A6(D7)* B5(D5)* C1(BUSY)* C3(DNC2)* C4(DNC3)* C5(D4)* D2(~{CEO})* D3(DNC10)* D4(DNC11)* D5(D3)* E3(DNC4)* E4(DNC5)* E5(D2)* F2(DNC6)* F3(DNC7)* F4(DNC8)* G2(DNC9)* H5(D1)*; U11 W11(D_OUT_BUSY_0)*; U13 51(V12_SWL0)* 52(V12_SWL1)* 54(VCC)*; U14 51(V12_SWL0)* 52(V12_SWL1)* 54(VCC)*

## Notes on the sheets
sheet 11
- 2.5V
- 2.5V
- 2.5V
- 2.5V
- 2.5V
- 2.5V
- R278 and R280 are installed for
  SPI FLASH MODE: 0x03
  FS0: 1
  FS1: 0
  FS2: 1
- FS0
- FS1
- FS2
- When PWR_FLOAT goes high, the DMD
  mirrors will float.  The board must be power
   cycled to unfloat.
- V5_PWR_FLOAT#    PWRGD     PWR_FLOAT
- 0
  0
  1
  1
- 0
  1
  0
  1
- 1
  1
  1
  0
- DLPC410 2
- DLP010
sheet 12
- 3.3V
- NOTE: Do Not Install
- NOTE:
  Do Not Install
- Configuration Mode
- M[2:0]
- Primary Serial
  Primary SPI
  Primary BPI-Up
  Primary BPI-Down
  Primary SelectMAP
  JTAG
  Secondary SelectMAP
  Secondary Serial (Default)
- 000
  001
  010
  011
  100
  101
  110
  111
- 0-1 REVISION SELECT = 00
  1-2 REVISION SELECT = 01
- Place jumper on J23 and J24 to program
  U24 with Cheetah SPI Programmer.
- NOTE:
  Primary Serial configuration
  is used for SPI PROM configuration.
  Secondary Serial is used for secure
  PROM configuration (i.e, DLPR410
  and XCF16 are used).
  Refer to AMD-Xilinx Virtex 5 Configuration Guide.
- NOTE:
  Do Not Install
- SPI CONFIG FLASH
- NOTE: Do Not Install
- MOSI
- Red
- NOTE: Do Not Install
- Green
- FCS_B
- NOTE: Do Not Install
- DLPC410 3
- DLP010
sheet 13
- Configured for ID = 00
- NOTE: Do Not Install
- NOTE: Do Not Install
- NOTE: A zener is required on
  either the controller or the DMD
  board, but NOT both.
- Note: The thermal pad (THPAD) is connected internally to VRESET_RAIL.
  Do Not Connect the thermal pad (THPAD) to Ground.
- DLPA200 A
- DLP010
sheet 14
- Configured for ID = 00
- NOTE: Do Not Install
- NOTE: Do Not Install
- 0-1 DAD2 Outputs Disabled
  1-2 DAD2 Outputs Enabled
- Note: The thermal pad (THPAD) is connected internally to VRESET_RAIL.
  Do Not Connect the Thermal Pad (THPAD) to Ground.
- DLPA200 B
- DLP010
sheet 15
- FLEX CONNECTOR A
- NOTE: Do Not Install
- DMD FLEX A
- DLP010
